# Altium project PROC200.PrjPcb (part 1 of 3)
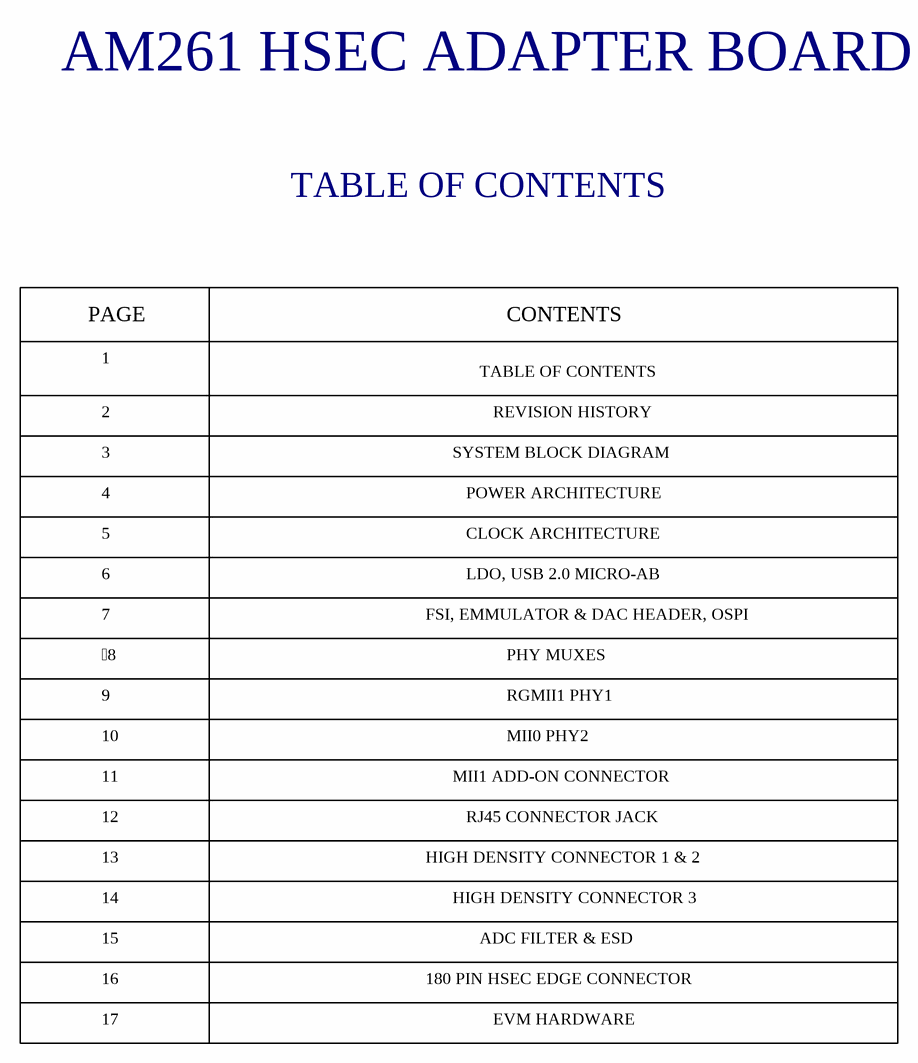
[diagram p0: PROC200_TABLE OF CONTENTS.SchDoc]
DrawnBy: Texas Instruments; EVM_orderable: HSEC180ADAPEVM-AM2; PCB_Rev: E1; PRJ_Customer: Public Release; PRJ_Number: PROC200; PRJ_Title: AM261 HSEC Adapter Board; SCH_REV: E1
18 sheets, 363 parts. Net scope: global (net labels, ports and power ports of the same name join across sheets).
Board file: PROC200E1.PcbDoc
Sheets:
  PROC200_TABLE OF CONTENTS.SchDoc
  PROC200_REVISION_HISTORY.SchDoc
  PROC200_SYSTEM_BLOCK_DIAGRAM.SchDoc
  PROC200_POWER_ARCHITECTURE.SchDoc
  PROC200_CLOCK_ARCHITECTURE.SchDoc
  PROC200_RESET_SIGNAL_ARCHITECTURE.SchDoc
  PROC200_LDO_USB_MICRO-AB.SchDoc
  PROC200_OSPI_FSI _DAC_Emmulator_Header.SchDoc
  PROC200_PHY_MUX.SchDoc
  PROC200_RGMII1_PHY1.SchDoc
  PROC200_MII0_PHY2.SchDoc
  PROC200_MII1_ADD_ON_CONN.SchDoc
  PROC200_RJ45_1_2.SchDoc
  PROC200_High_Density_conn1_2.SchDoc
  PROC200_High_Density_conn3.SchDoc
  PROC200_HSEC_ADC.SchDoc
  PROC200_180pin_Edge_Connector.SchDoc
  PROC200_EVM_Hardware.SchDoc

## Sheet PROC200_TABLE OF CONTENTS.SchDoc
size 431 x 279 mm; Date: Not shown in title block; ApprovedBy: Not shown in title block; CheckedBy: Not shown in title block; Author: Not shown in title block; CompanyName: Not shown in title block; Engineer: Not shown in title block; Organization: Not shown in title block; Address1: Not shown in title block; Address2: Not shown in title block; Address3: Not shown in title block; Address4: Not shown in title block; DocumentNumber: 1; Revision: Use project parameter SCH_Rev; SheetNumber: 1; SheetTotal: 17; PageSetup: Record=PageOptions¦CenterHorizontal=True¦CenterVertical=True¦PrintScale=1.00¦XCorrection=1.00¦YCorrection=1.00¦PrintKind=0¦BorderSize=5000000¦LeftOffset=0¦BottomOffset=0¦Orientation=2¦PaperLength=1000¦PaperWidth=1000¦Scale=100¦PaperSource=15¦PrintQuality=600¦MediaType=1¦DitherType=10¦PaperKind=Letter¦PrintScaleMode=1

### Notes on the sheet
- AM261 HSEC ADAPTER BOARD
- TABLE OF CONTENTS
- PAGE
- 1
- CONTENTS
- 2
- REVISION HISTORY
- 3
- 4
- SYSTEM BLOCK DIAGRAM
- POWER ARCHITECTURE
- 5
- 6
- LDO, USB 2.0 MICRO-AB
- CLOCK ARCHITECTURE
- 7
- FSI, EMMULATOR & DAC HEADER, OSPI
- 8
- 9
- PHY MUXES
- RGMII1 PHY1
- 10
- 11
- MII1 ADD-ON CONNECTOR
- MII0 PHY2
- 12
- RJ45 CONNECTOR JACK
- 13
- 14
- HIGH DENSITY CONNECTOR 1 & 2
- HIGH DENSITY CONNECTOR 3
- 15
- 16
- 180 PIN HSEC EDGE CONNECTOR
- ADC FILTER & ESD
- 17
- EVM HARDWARE

## Sheet PROC200_REVISION_HISTORY.SchDoc
size 431 x 279 mm; Date: Not shown in title block; ApprovedBy: Not shown in title block; CheckedBy: Not shown in title block; Author: Not shown in title block; CompanyName: Not shown in title block; Engineer: Not shown in title block; Organization: Not shown in title block; Address1: Not shown in title block; Address2: Not shown in title block; Address3: Not shown in title block; Address4: Not shown in title block; DocumentNumber: 2; Revision: Use project parameter SCH_Rev; SheetNumber: 2; SheetTotal: 17; PageSetup: Record=PageOptions¦CenterHorizontal=True¦CenterVertical=True¦PrintScale=1.00¦XCorrection=1.00¦YCorrection=1.00¦PrintKind=0¦BorderSize=5000000¦LeftOffset=0¦BottomOffset=0¦Orientation=2¦PaperLength=1000¦PaperWidth=1000¦Scale=100¦PaperSource=15¦PrintQuality=600¦MediaType=1¦DitherType=10¦PaperKind=Letter¦PrintScaleMode=1
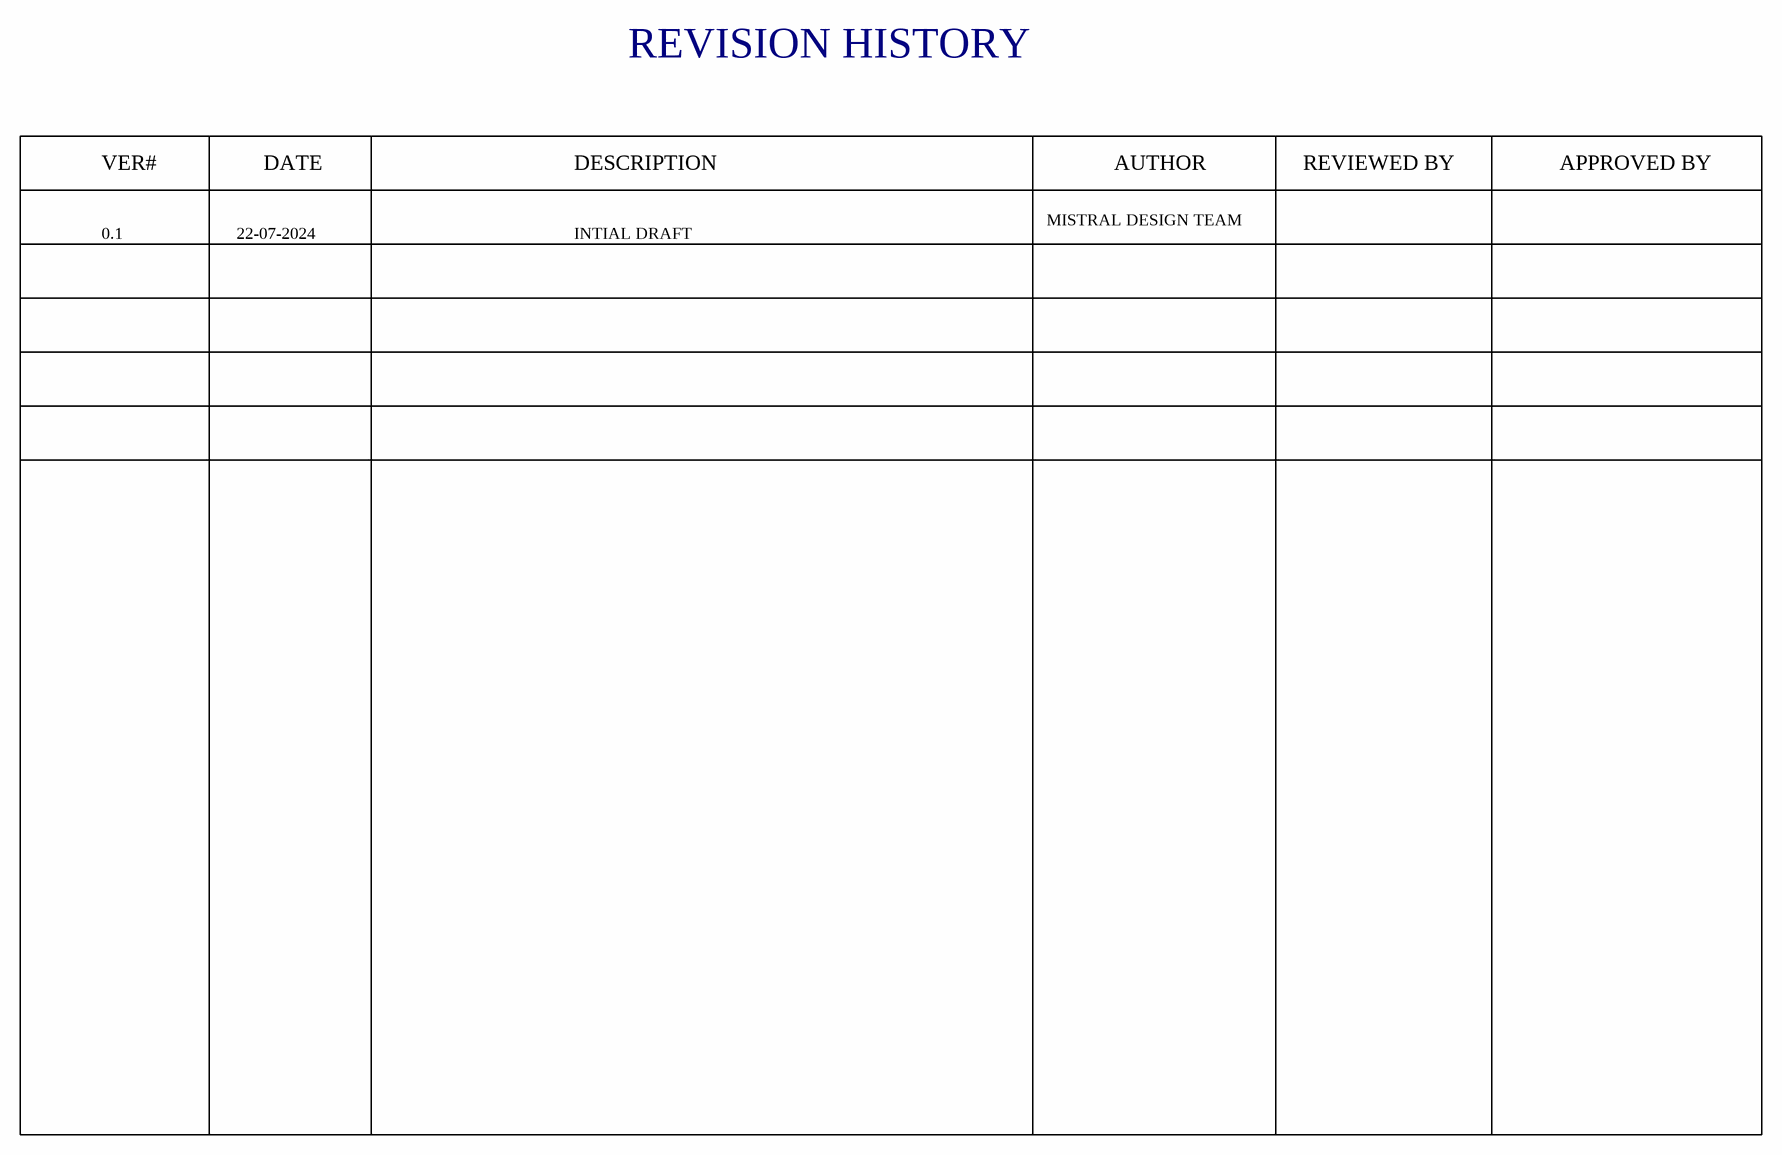
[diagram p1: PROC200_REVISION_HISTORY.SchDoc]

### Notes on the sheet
- REVISION HISTORY
- VER#
- DATE
- DESCRIPTION
- AUTHOR
- REVIEWED BY
- APPROVED BY
- 0.1
- 22-07-2024
- INTIAL DRAFT
- MISTRAL DESIGN TEAM

## Sheet PROC200_SYSTEM_BLOCK_DIAGRAM.SchDoc
size 431 x 279 mm; Date: Not shown in title block; ApprovedBy: Not shown in title block; CheckedBy: Not shown in title block; Author: Not shown in title block; CompanyName: Not shown in title block; Engineer: Not shown in title block; Organization: Not shown in title block; Address1: Not shown in title block; Address2: Not shown in title block; Address3: Not shown in title block; Address4: Not shown in title block; DocumentNumber: 3; Revision: Use project parameter SCH_Rev; SheetNumber: 3; SheetTotal: 17; PageSetup: Record=PageOptions¦CenterHorizontal=True¦CenterVertical=True¦PrintScale=1.00¦XCorrection=1.00¦YCorrection=1.00¦PrintKind=0¦BorderSize=5000000¦LeftOffset=0¦BottomOffset=0¦Orientation=2¦PaperLength=1000¦PaperWidth=1000¦Scale=100¦PaperSource=15¦PrintQuality=600¦MediaType=1¦DitherType=10¦PaperKind=Letter¦PrintScaleMode=1
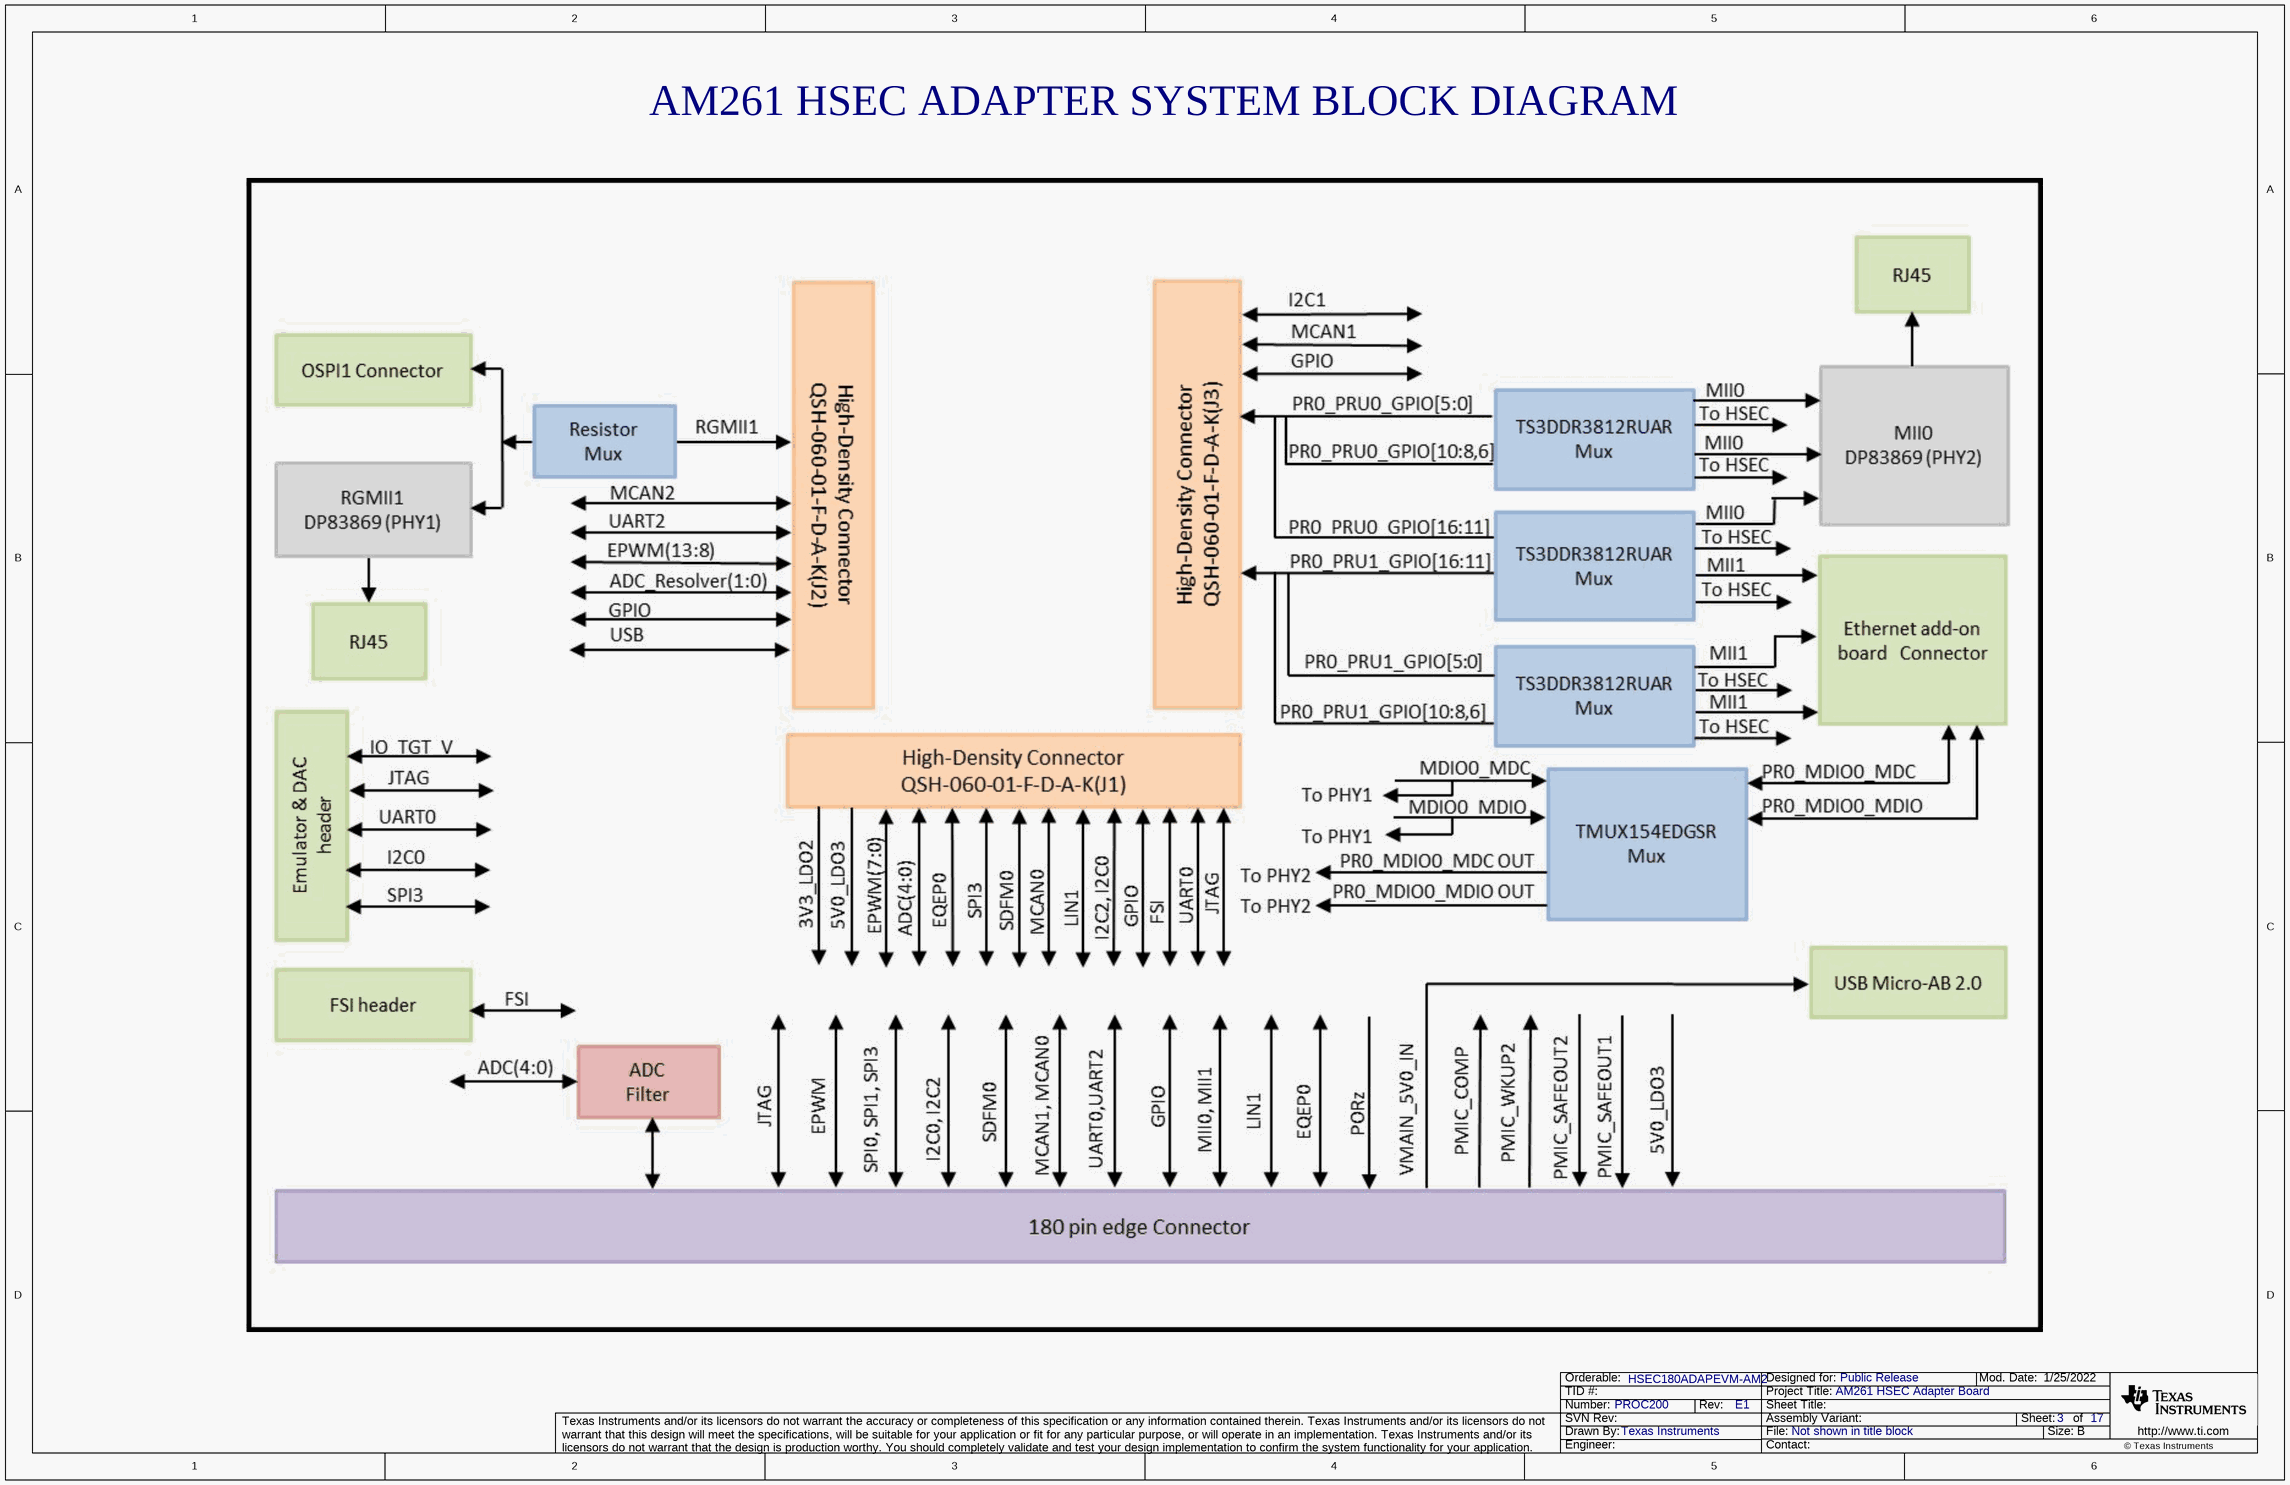
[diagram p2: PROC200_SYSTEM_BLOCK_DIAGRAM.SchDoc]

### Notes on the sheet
- AM261 HSEC ADAPTER SYSTEM BLOCK DIAGRAM

## Sheet PROC200_POWER_ARCHITECTURE.SchDoc
size 431 x 279 mm; Date: Not shown in title block; ApprovedBy: Not shown in title block; CheckedBy: Not shown in title block; Author: Not shown in title block; CompanyName: Not shown in title block; Engineer: Not shown in title block; Organization: Not shown in title block; Address1: Not shown in title block; Address2: Not shown in title block; Address3: Not shown in title block; Address4: Not shown in title block; DocumentNumber: 4; Revision: Use project parameter SCH_Rev; SheetNumber: 4; SheetTotal: 17; PageSetup: Record=PageOptions¦CenterHorizontal=True¦CenterVertical=True¦PrintScale=1.00¦XCorrection=1.00¦YCorrection=1.00¦PrintKind=0¦BorderSize=5000000¦LeftOffset=0¦BottomOffset=0¦Orientation=2¦PaperLength=1000¦PaperWidth=1000¦Scale=100¦PaperSource=15¦PrintQuality=600¦MediaType=1¦DitherType=10¦PaperKind=Letter¦PrintScaleMode=1
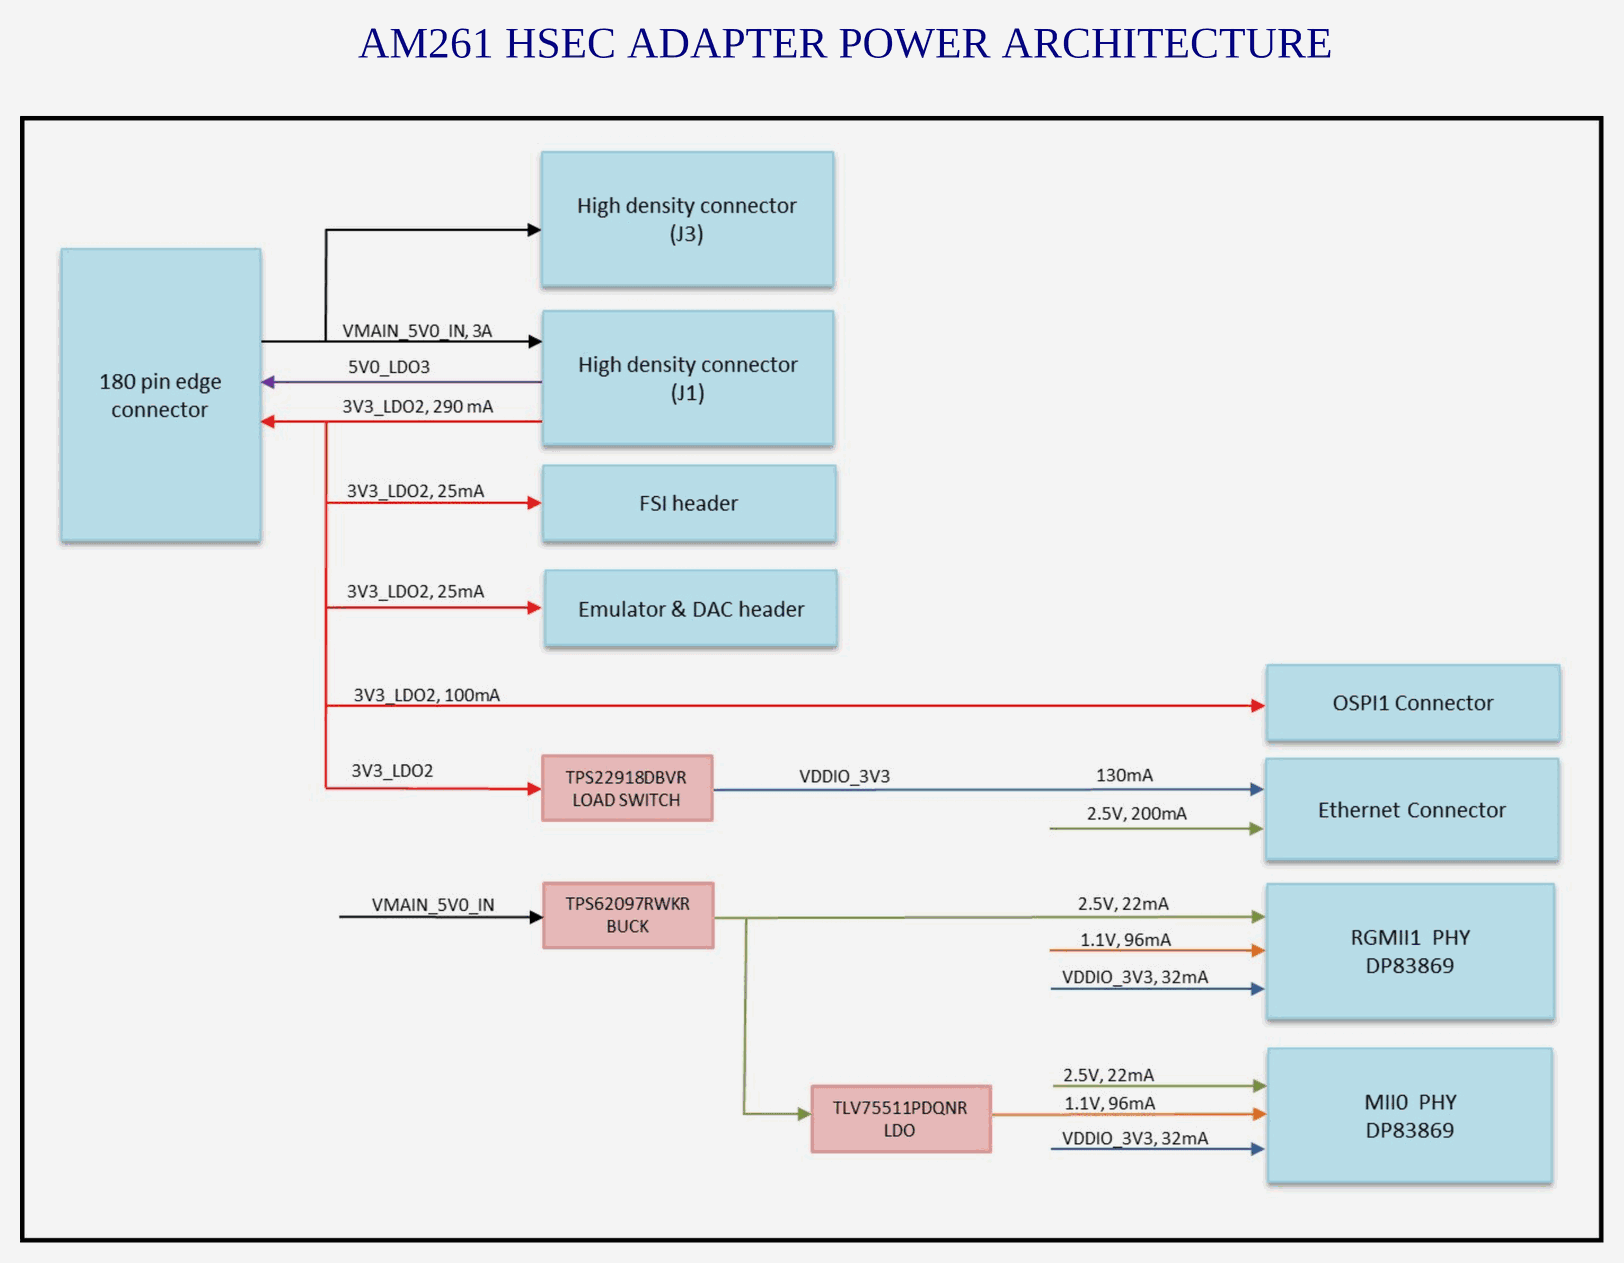
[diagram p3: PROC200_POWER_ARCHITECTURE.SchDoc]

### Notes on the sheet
- AM261 HSEC ADAPTER POWER ARCHITECTURE

## Sheet PROC200_CLOCK_ARCHITECTURE.SchDoc
size 431 x 279 mm; Date: Not shown in title block; ApprovedBy: Not shown in title block; CheckedBy: Not shown in title block; Author: Not shown in title block; CompanyName: Not shown in title block; Engineer: Not shown in title block; Organization: Not shown in title block; Address1: Not shown in title block; Address2: Not shown in title block; Address3: Not shown in title block; Address4: Not shown in title block; DocumentNumber: 1; Revision: Use project parameter SCH_Rev; SheetNumber: 5; SheetTotal: 17; PageSetup: Record=PageOptions¦CenterHorizontal=True¦CenterVertical=True¦PrintScale=1.00¦XCorrection=1.00¦YCorrection=1.00¦PrintKind=0¦BorderSize=5000000¦LeftOffset=0¦BottomOffset=0¦Orientation=2¦PaperLength=1000¦PaperWidth=1000¦Scale=100¦PaperSource=15¦PrintQuality=600¦MediaType=1¦DitherType=10¦PaperKind=Letter¦PrintScaleMode=1
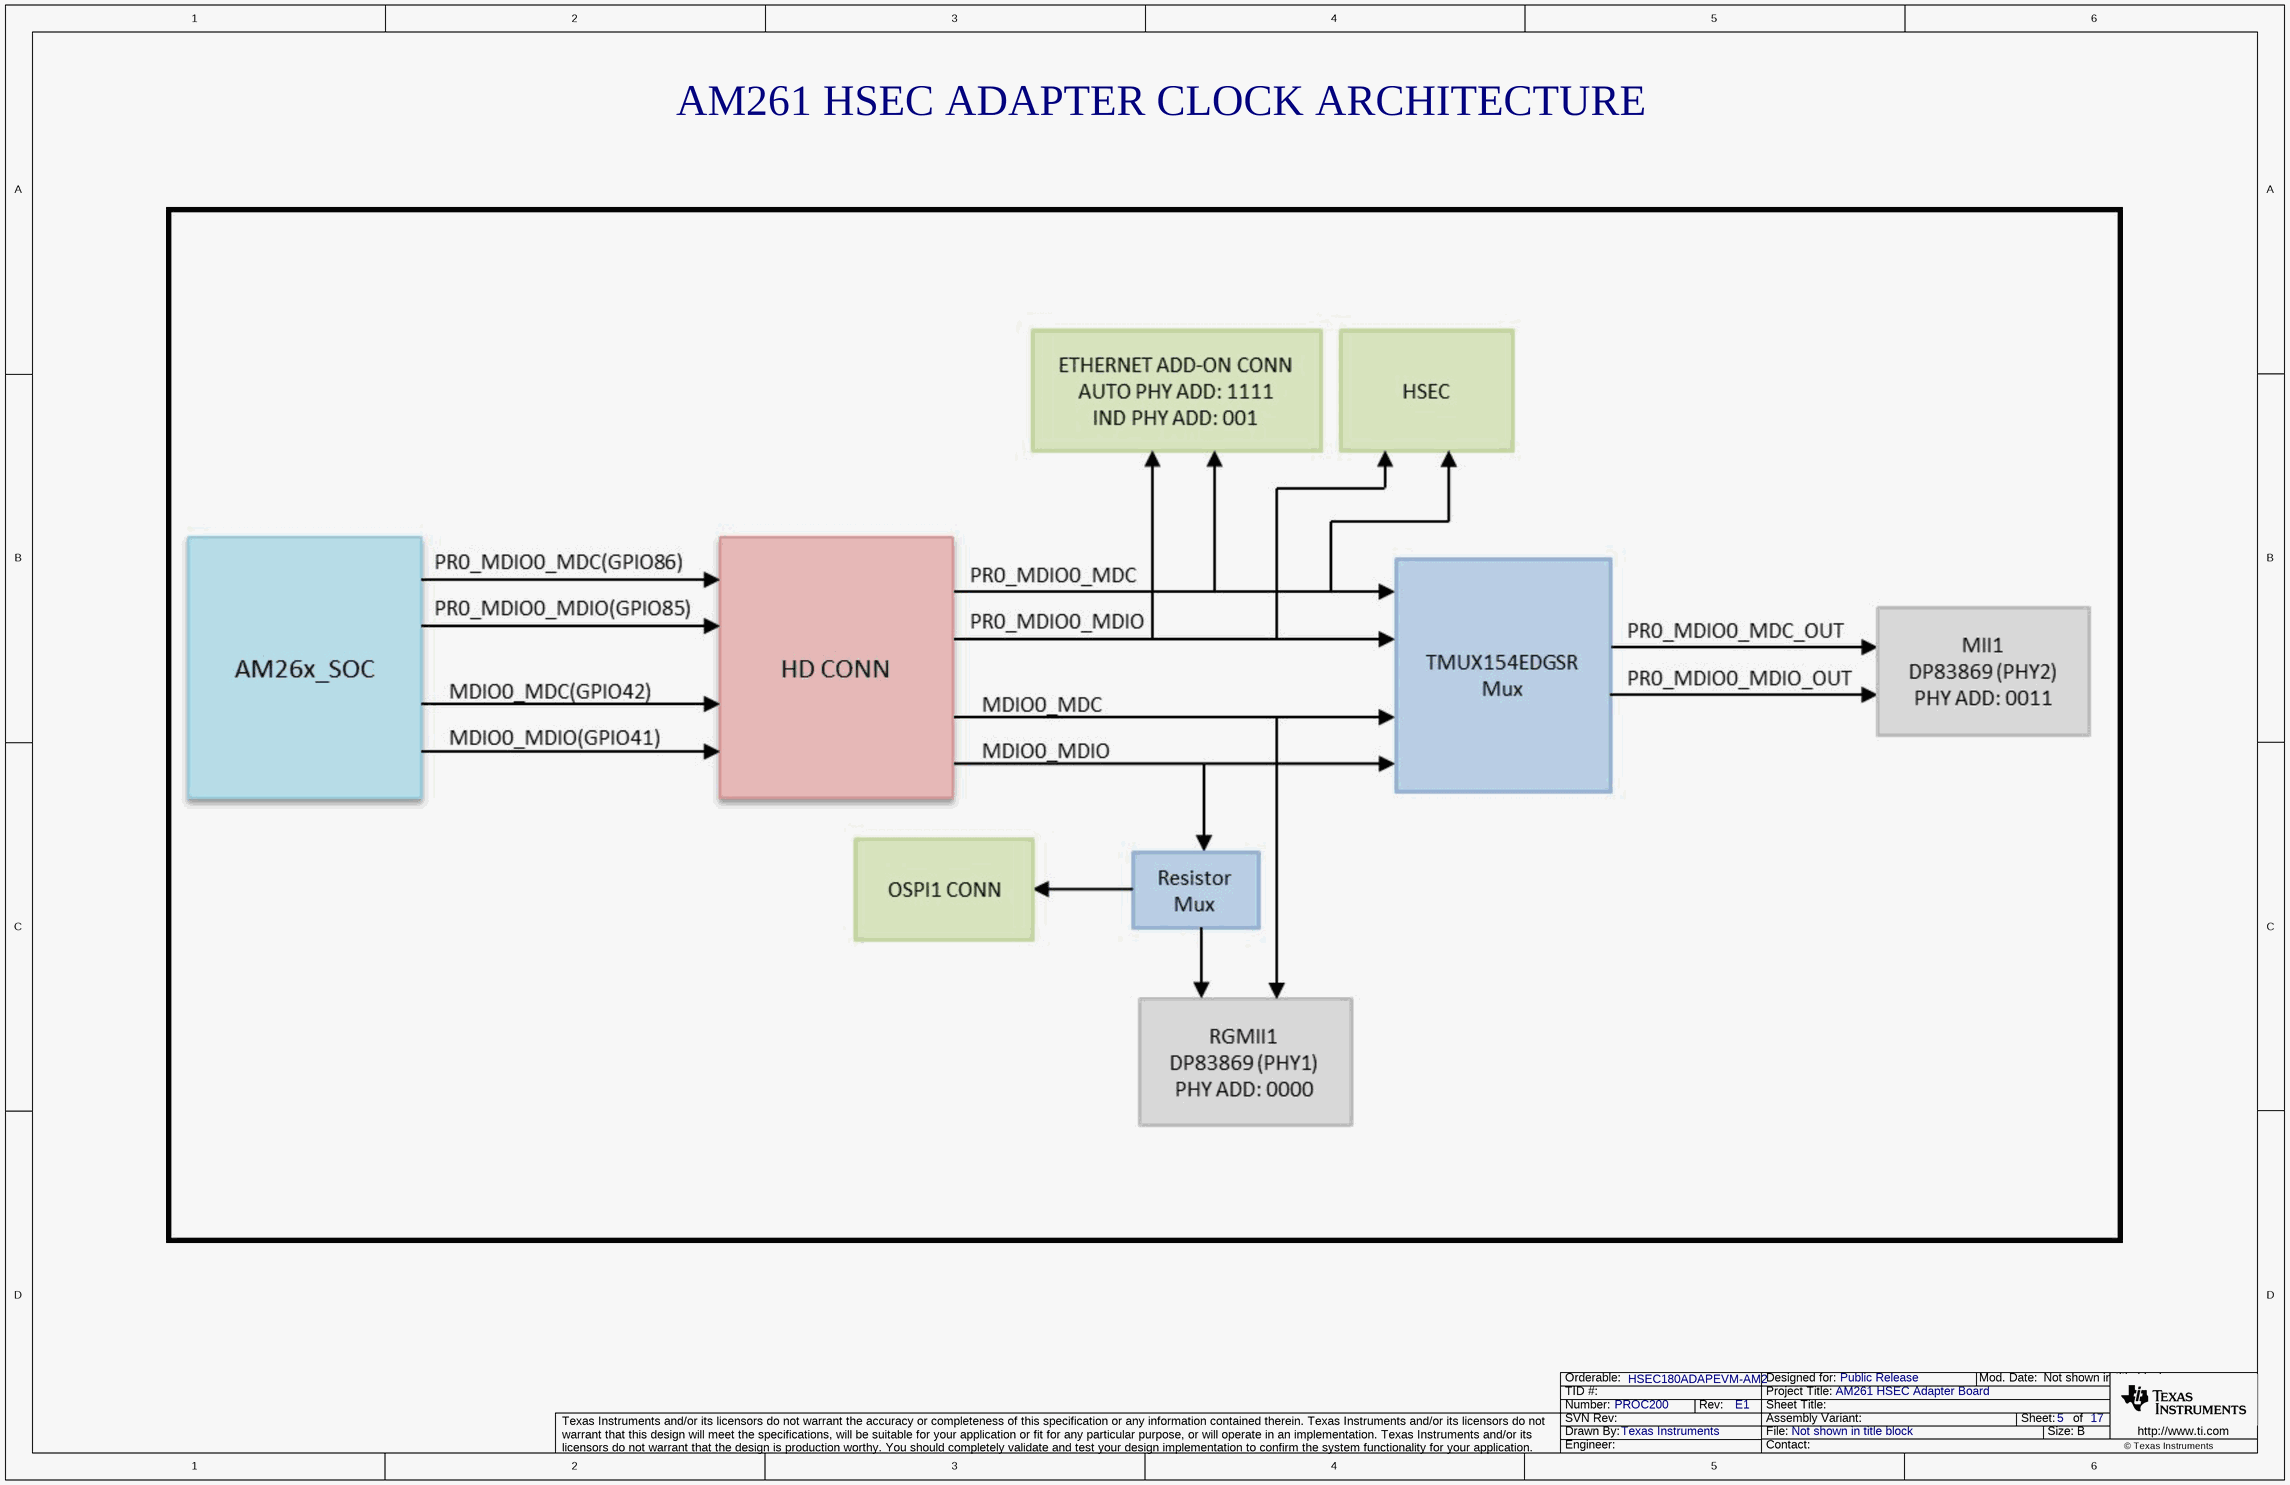
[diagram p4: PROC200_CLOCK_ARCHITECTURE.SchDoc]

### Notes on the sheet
- AM261 HSEC ADAPTER CLOCK ARCHITECTURE

## Sheet PROC200_RESET_SIGNAL_ARCHITECTURE.SchDoc
size 431 x 279 mm; Date: Not shown in title block; ApprovedBy: Not shown in title block; CheckedBy: Not shown in title block; Author: Not shown in title block; CompanyName: Not shown in title block; Engineer: Not shown in title block; Organization: Not shown in title block; Address1: Not shown in title block; Address2: Not shown in title block; Address3: Not shown in title block; Address4: Not shown in title block; DocumentNumber: 1; Revision: Use project parameter SCH_Rev; SheetNumber: 6; SheetTotal: 18; PageSetup: Record=PageOptions¦CenterHorizontal=True¦CenterVertical=True¦PrintScale=1.00¦XCorrection=1.00¦YCorrection=1.00¦PrintKind=0¦BorderSize=5000000¦LeftOffset=0¦BottomOffset=0¦Orientation=2¦PaperLength=1000¦PaperWidth=1000¦Scale=100¦PaperSource=15¦PrintQuality=600¦MediaType=1¦DitherType=10¦PaperKind=Letter¦PrintScaleMode=1
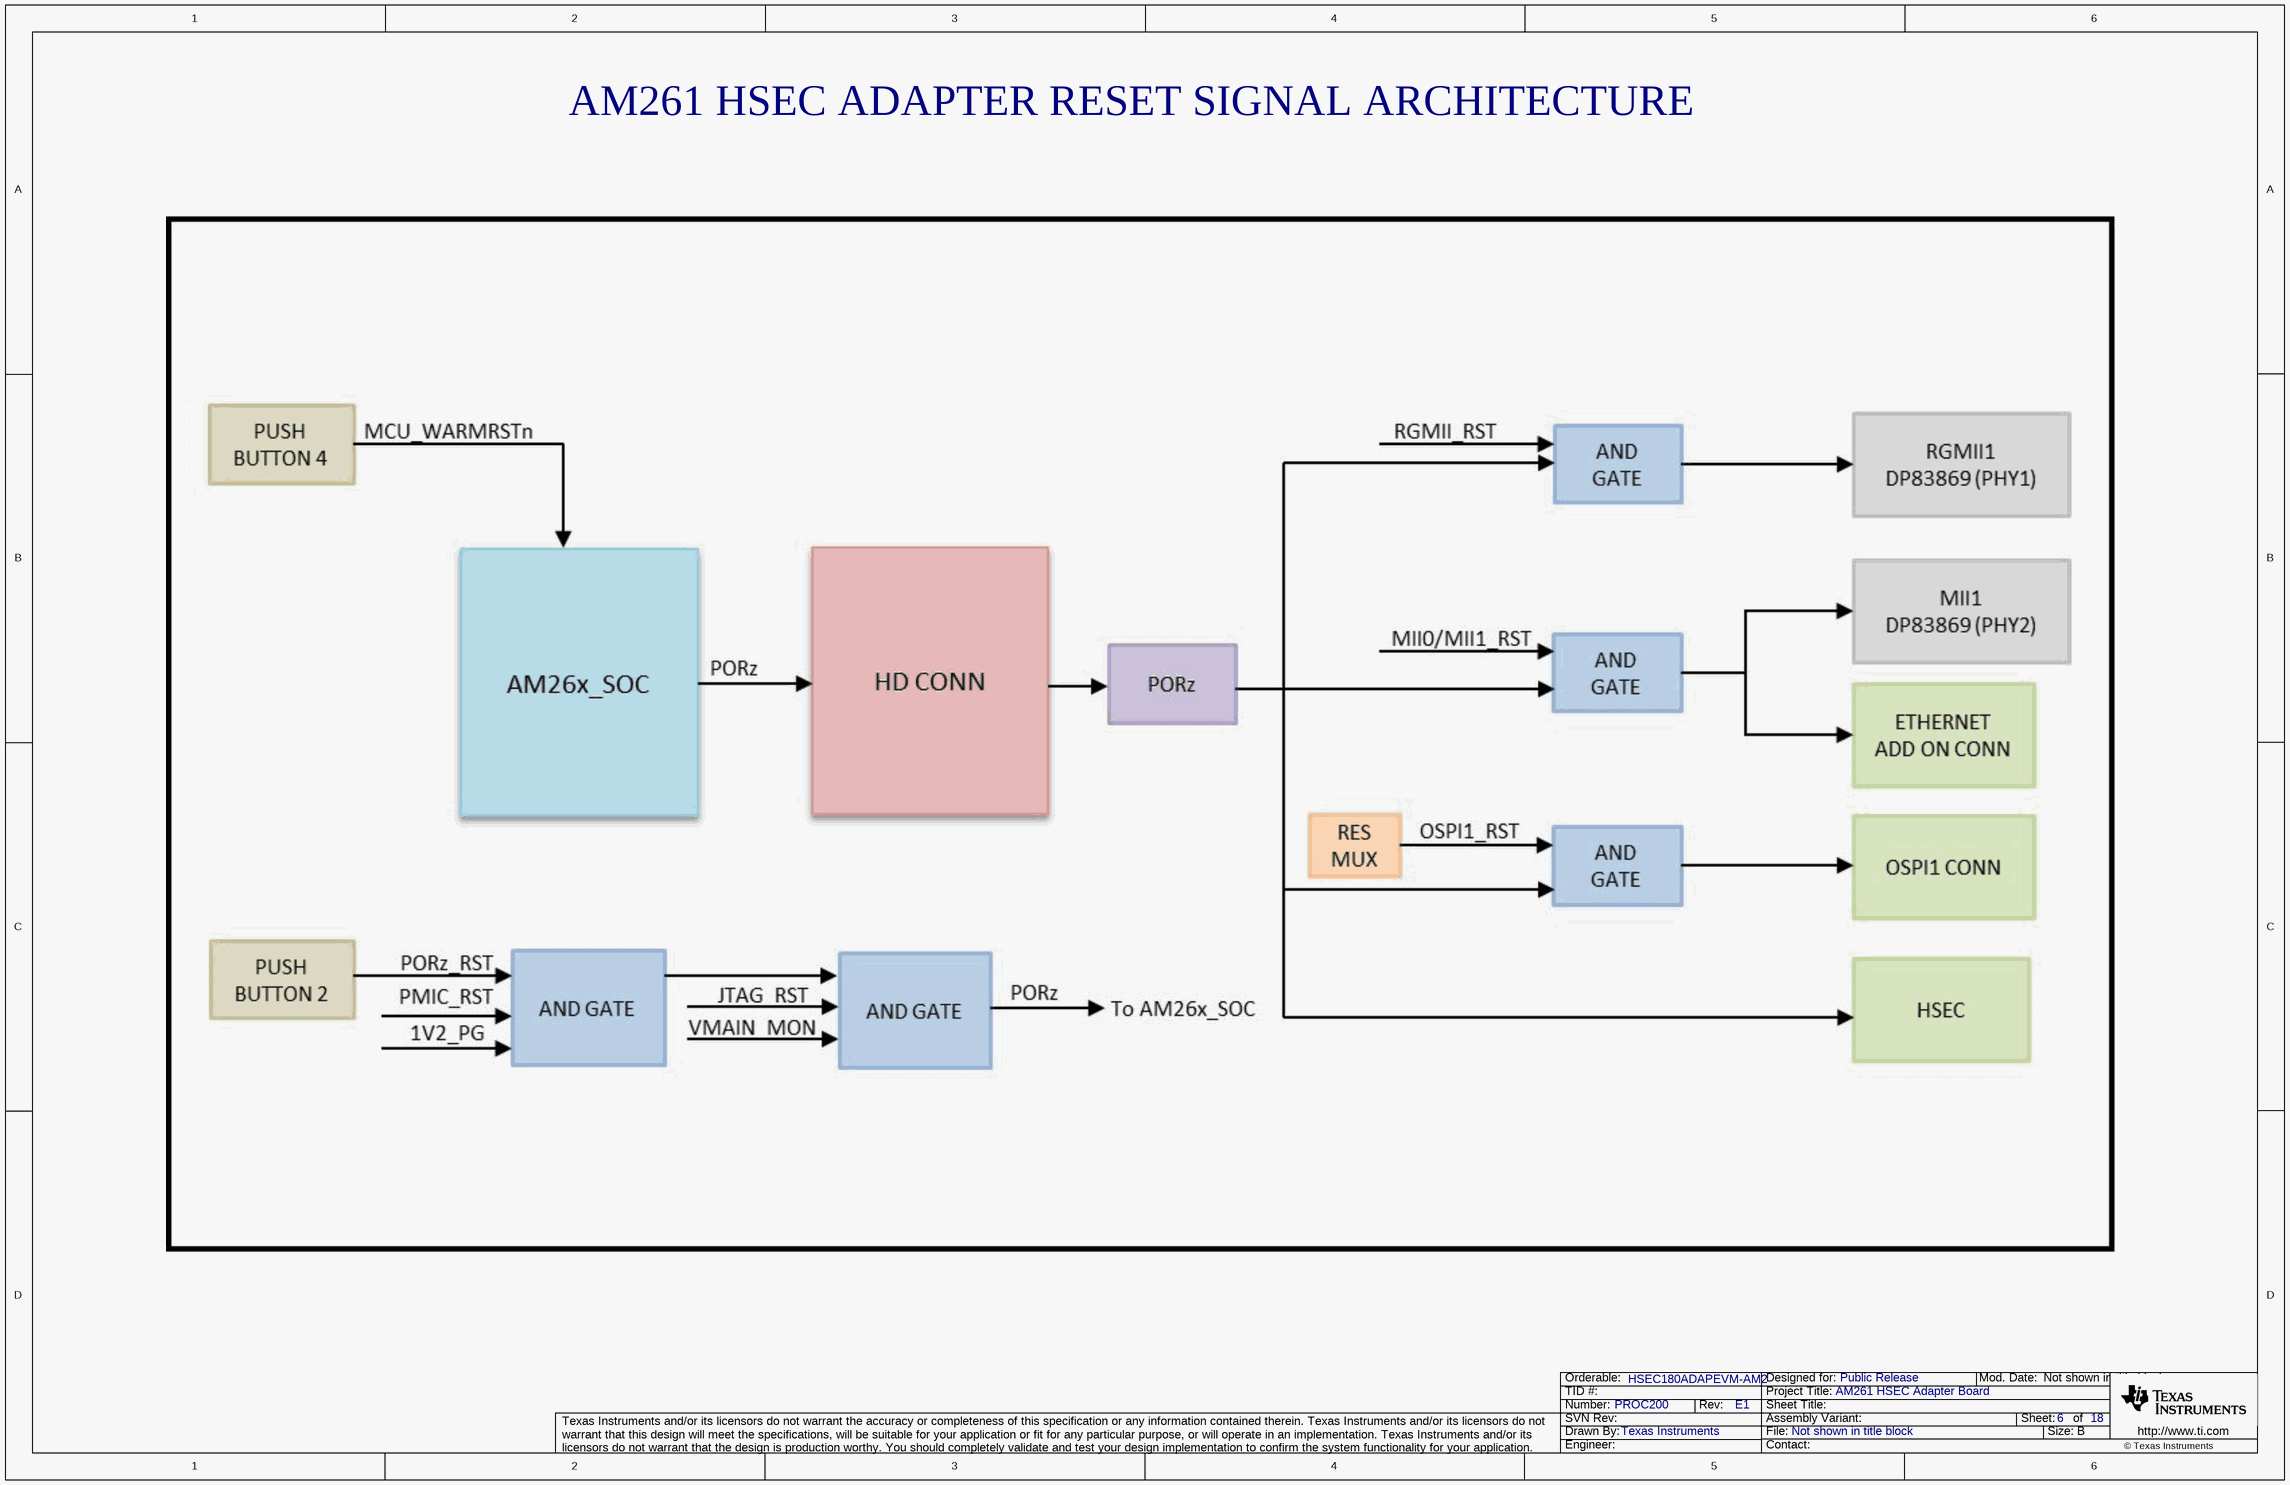
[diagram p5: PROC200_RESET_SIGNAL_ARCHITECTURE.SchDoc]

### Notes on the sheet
- AM261 HSEC ADAPTER RESET SIGNAL ARCHITECTURE

## Sheet PROC200_LDO_USB_MICRO-AB.SchDoc
size 431 x 279 mm; SheetNumber: 7; SheetTotal: 18
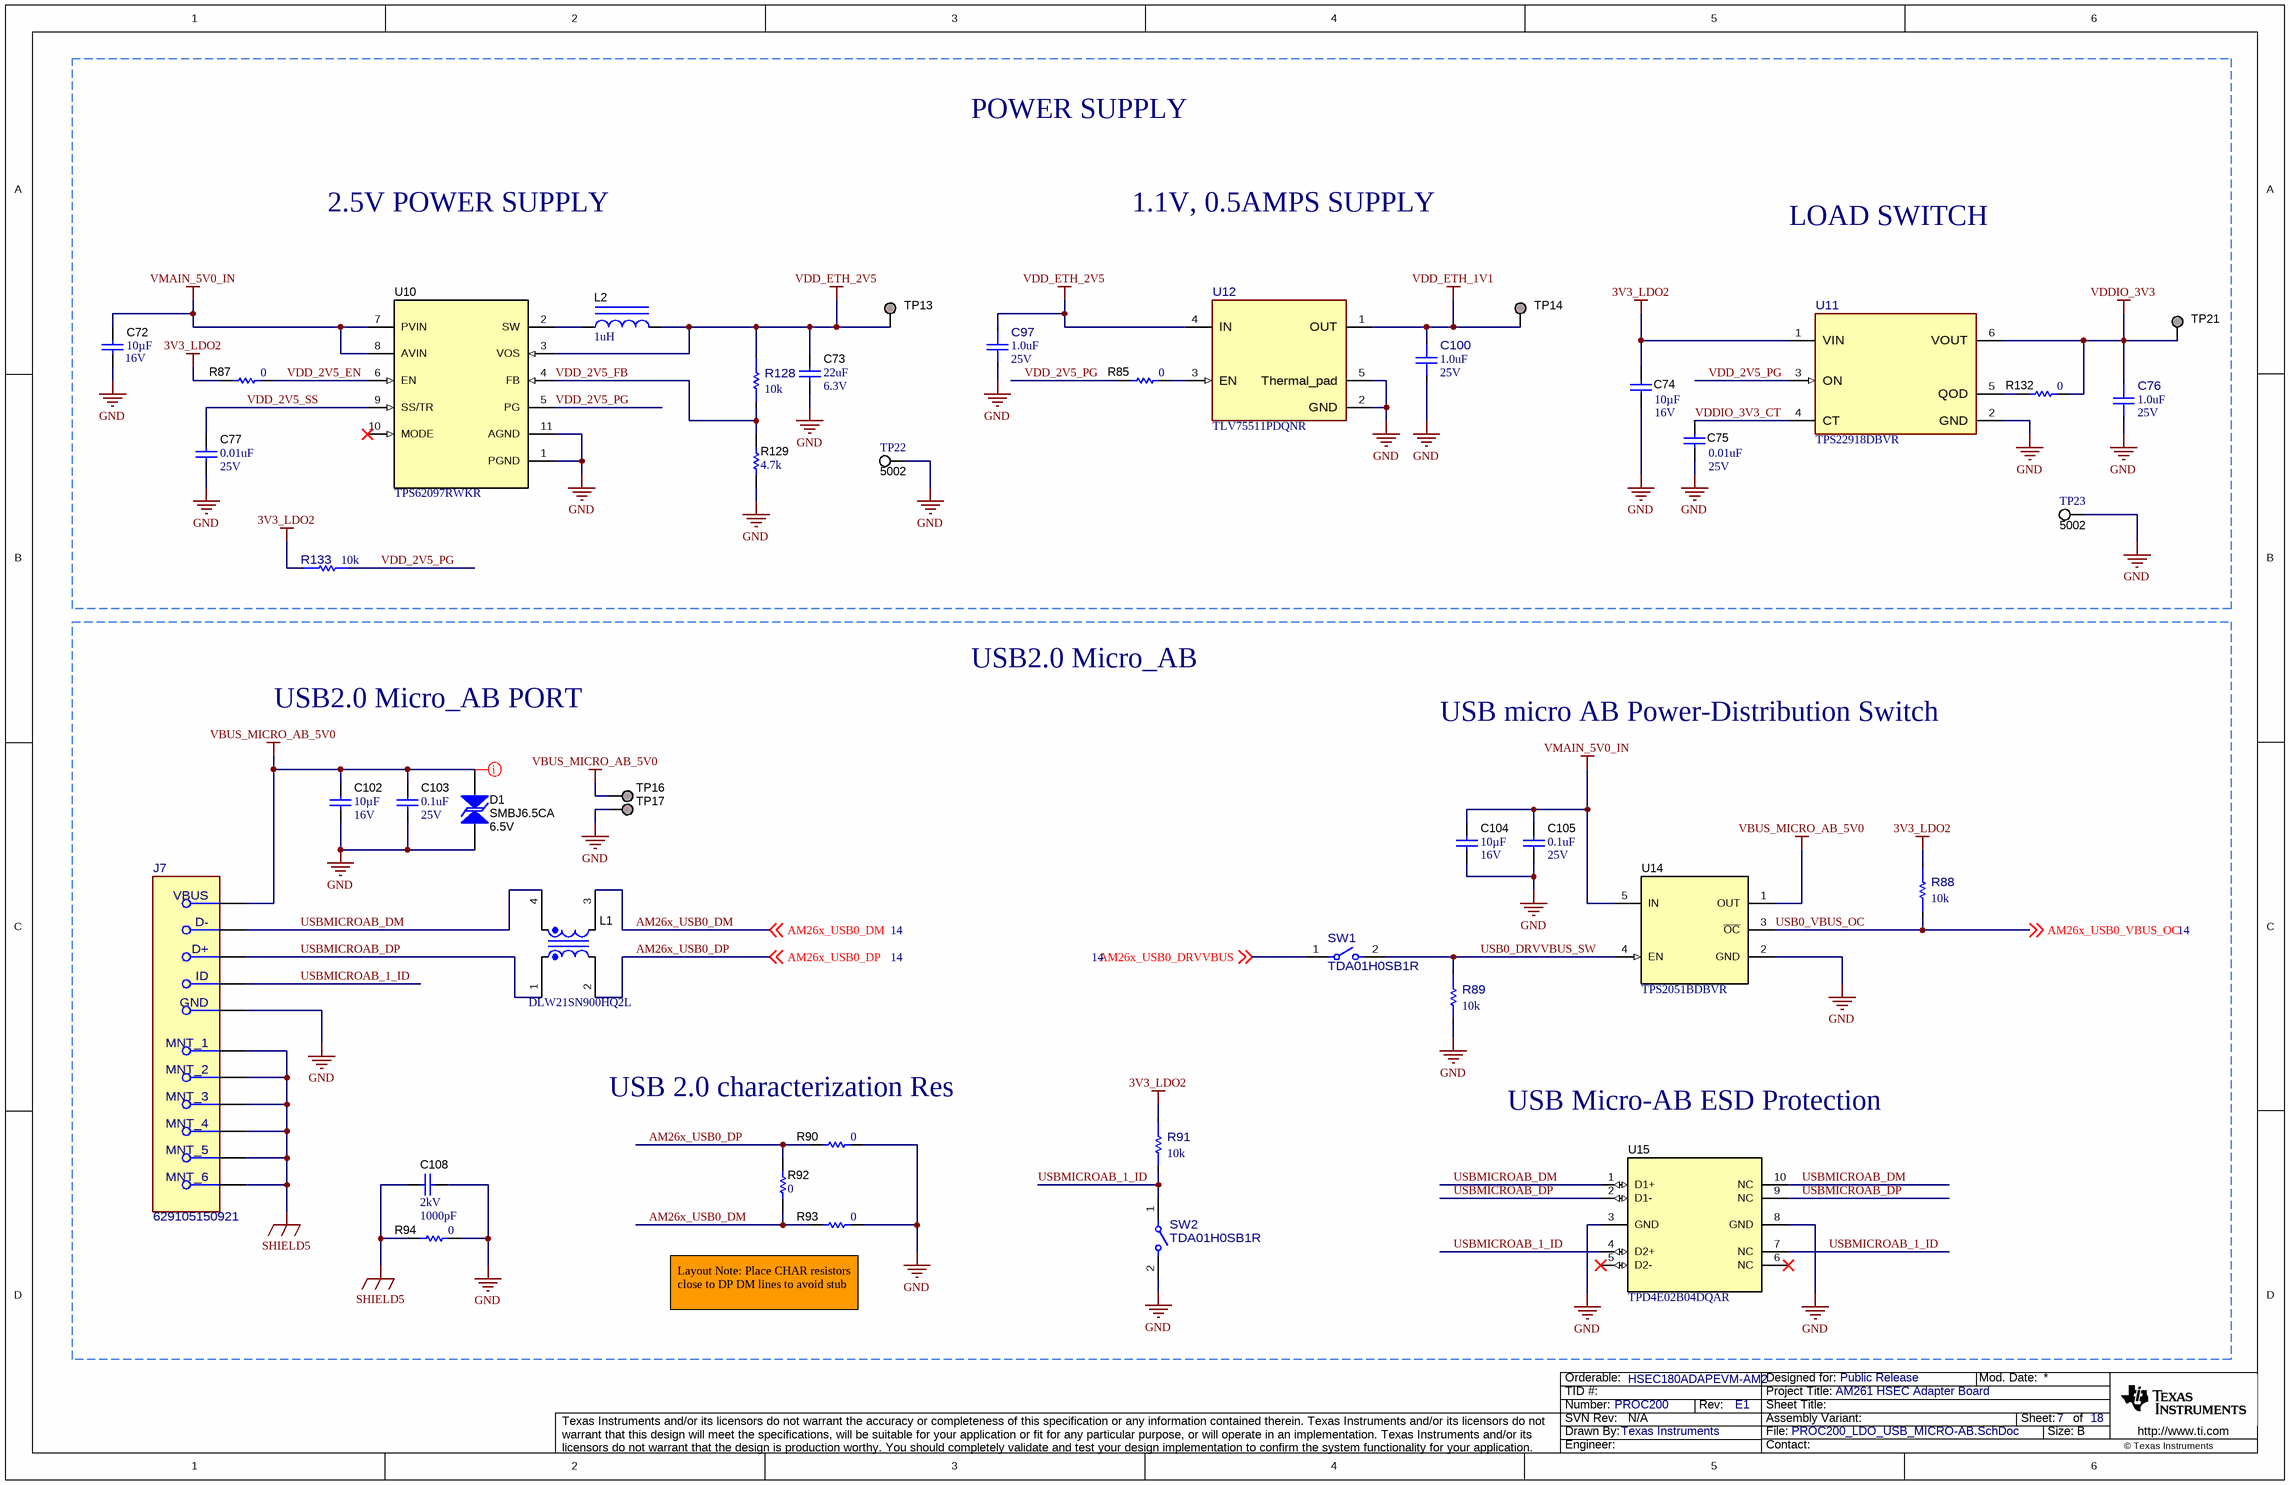
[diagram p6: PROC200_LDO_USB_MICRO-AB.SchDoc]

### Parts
C72  VDC_V: 16V  ValueDisplayed: 10µF  [0603]  (hidden comment: GRM188C81C106MA73D)
C73  VDC_V: 6.3V  ValueDisplayed: 22uF  [0603]  (hidden comment: GRM188R60J226MEA0D)
C74  VDC_V: 16V  ValueDisplayed: 10µF  [0603]  (hidden comment: GRM188C81C106MA73D)
C75  Value2: 25V  ValueDisplayed: 0.01uF  [0402]  (hidden comment: GCM155R71E103KA37D)
C76  ValueDisplayed: 1.0uF  VDC_V: 25V  [FP-GRM155C81E105KE11D_0402-MFG]  (hidden comment: GRM155C81E105KE11D)
C77  Value2: 25V  ValueDisplayed: 0.01uF  [0402]  (hidden comment: GCM155R71E103KA37D)
C97  ValueDisplayed: 1.0uF  VDC_V: 25V  [FP-GRM155C81E105KE11D_0402-MFG]  (hidden comment: GRM155C81E105KE11D)
C100  ValueDisplayed: 1.0uF  VDC_V: 25V  [FP-GRM155C81E105KE11D_0402-MFG]  (hidden comment: GRM155C81E105KE11D)
C102  VDC_V: 16V  ValueDisplayed: 10µF  [0603]  (hidden comment: GRM188C81C106MA73D)
C103  VDC_V: 25V  ValueDisplayed: 0.1uF  [0402]  (hidden comment: GRM155R71E104KE14D)
C104  VDC_V: 16V  ValueDisplayed: 10µF  [0603]  (hidden comment: GRM188C81C106MA73D)
C105  Value2: 25V  ValueDisplayed: 0.1uF  [0402]  (hidden comment: GRM155R71E104KE14D)
C108  VDC_V: 2kV  ValueDisplayed: 1000pF  [1808]  (hidden comment: GR442QR73D102KW01L)
D1  SMBJ6.5CA  value 6.5V  [SMB-Bi]
J7  629105150921  [FP-629105150921_CONN_PTH_USB_8MM0_5MM6-MFG]
L1  DLW21SN900HQ2L  [IND_DLW21S]
L2  ValueDisplayed: 1uH  [IHLP-2020BZ]  (hidden comment: IHLP2020BZER1R0M01)
R85  ValueDisplayed: 0  [0402]  (hidden comment: ERJ-2GE0R00X)
R87  ValueDisplayed: 0  [0402]  (hidden comment: ERJ-2GE0R00X)
R88  value 10k  [FP-RC0402JR-0710KL_0402-MFG]  (hidden comment: RC0402JR-0710KL)
R89  value 10k  [FP-RC0402JR-0710KL_0402-MFG]  (hidden comment: RC0402JR-0710KL)
R90  ValueDisplayed: 0  [0402]  (hidden comment: ERJ-2GE0R00X)
R91  value 10k  [FP-RC0402JR-0710KL_0402-MFG]  (hidden comment: RC0402JR-0710KL)
R92  ValueDisplayed: 0  [0402]  (hidden comment: ERJ-2GE0R00X)
R93  ValueDisplayed: 0  [0402]  (hidden comment: ERJ-2GE0R00X)
R94  ValueDisplayed: 0  [0805_HV]  (hidden comment: ERJ-6GEY0R00V)
R128  value 10k  [FP-RC0402JR-0710KL_0402-MFG]  (hidden comment: RC0402JR-0710KL)
R129  ValueDisplayed: 4.7k  [0402]  (hidden comment: CRCW04024K70JNED)
R132  ValueDisplayed: 0  [0402]  (hidden comment: ERJ-2GE0R00X)
R133  value 10k  [FP-RC0402JR-0710KL_0402-MFG]  (hidden comment: RC0402JR-0710KL)
SW1  TDA01H0SB1R  [FP-TDA01H0SB1R_SMT_SW_2MM40_6MM20-MFG]
SW2  TDA01H0SB1R  [FP-TDA01H0SB1R_SMT_SW_2MM40_6MM20-MFG]
TP13  TESTPOINT  [TP_25MIL-SMT]  (value not drawn)  (no BOM)
TP14  TESTPOINT  [TP_25MIL-SMT]  (value not drawn)  (no BOM)
TP16  TESTPOINT  [TP_25MIL-SMT]  (value not drawn)  (no BOM)
TP17  TESTPOINT  [TP_25MIL-SMT]  (value not drawn)  (no BOM)
TP21  TESTPOINT  [TP_25MIL-SMT]  (value not drawn)  (no BOM)
TP22  5002  [Keystone5002]
TP23  5002  [Keystone5002]
U10  TPS62097RWKR  [RWK0011B]
U11  TPS22918DBVR  [DBV0006A-MFG]
U12  TLV75511PDQNR  [DQN0004A-MFG]
U14  TPS2051BDBVR  [DBV0005A_N]
U15  TPD4E02B04DQAR  [DQA0010A]

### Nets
3V3_LDO2: C74.2 R87.1 R88.1 R91.1 R133.1 U11.1(VIN)
GND: C72.1 C73.1 C74.1 C75.2 C76.2 C77.2 C97.2 C100.2 C102.1 C103.2 C104.1 C105.1 C108.1 D1.1 J7.5(GND) R89.2 R90.2 R93.2 R94.2 R129.2 SW2.2 TP17.1 TP22.1 TP23.1 U10.1(PGND) U10.11(AGND) U11.2(GND) U12.2(GND) U12.5(Thermal_pad) U14.2(GND) U15.3(GND) U15.8(GND)
SHIELD5: C108.2 J7.6(MNT_1) J7.7(MNT_2) J7.8(MNT_3) J7.9(MNT_4) J7.10(MNT_5) J7.11(MNT_6) R94.1
VBUS_MICRO_AB_5V0: C102.2 C103.1 D1.2 J7.1(VBUS) TP16.1 U14.1(OUT)
VDD_ETH_1V1: C100.1 TP14.1 U12.1(OUT)
VDD_ETH_2V5: C73.2 C97.1 L2.2 R128.1 TP13.1 U10.3(VOS) U12.4(IN)
VDDIO_3V3: C76.1 R132.2 TP21.1 U11.6(VOUT)
VMAIN_5V0_IN: C72.2 C104.2 C105.2 U10.7(PVIN) U10.8(AVIN) U14.5(IN)
AM26x_USB0_DM: L1.3 R92.1 R93.1 ; off-sheet AM26x_USB0_DM
AM26x_USB0_DP: L1.2 R90.1 R92.2 ; off-sheet AM26x_USB0_DP
AM26x_USB0_DRVVBUS: SW1.1 ; off-sheet AM26x_USB0_DRVVBUS
USB0_DRVVBUS_SW: R89.1 SW1.2 U14.4(EN)
USB0_VBUS_OC: R88.2 U14.3(~{OC}) ; off-sheet AM26x_USB0_VBUS_OC  [also labelled AM26x_USB0_VBUS_OC]
USBMICROAB_1_ID: J7.4(ID) R91.2 SW2.1 U15.4(D2+) U15.7(NC)
USBMICROAB_DM: J7.2(D-) L1.4 U15.1(D1+) U15.10(NC)
USBMICROAB_DP: J7.3(D+) L1.1 U15.2(D1-) U15.9(NC)
VDD_2V5_EN: R87.2 U10.6(EN)
VDD_2V5_FB: R128.2 R129.1 U10.4(FB)
VDD_2V5_PG: R85.1 R133.2 U10.5(PG) U11.3(ON)
VDD_2V5_SS: C77.1 U10.9(SS/TR)
VDDIO_3V3_CT: C75.1 U11.4(CT)
NetL2_1: L2.1 U10.2(SW)
NetR85_2: R85.2 U12.3(EN)
NetR132_1: R132.1 U11.5(QOD)

Not connected (* = marked no-connect by the designer): U10 10(MODE)*; U15 5(D2-)* 6(NC)*

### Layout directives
net class POWER: VBUS_MICRO_AB_5V0

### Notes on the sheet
- POWER SUPPLY
- 2.5V POWER SUPPLY
- 1.1V, 0.5AMPS SUPPLY
- LOAD SWITCH
- USB2.0 Micro_AB
- USB2.0 Micro_AB PORT
- USB micro AB Power-Distribution Switch
- (near R90) USB 2.0 characterization Res
- USB Micro-AB ESD Protection
- (near R93) Layout Note: Place CHAR resistors close to DP DM lines to avoid stub

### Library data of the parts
C72 C74 C102 C104 = CMP-0086062-1: CAP, CERM, 10 µF, 16 V,+/- 20%, X6S, 0603; Manufacturer: MuRata; U/M: EA; AEC Category: Q200; SizeX_mm: 1.6; SizeY_mm: 0.8; SizeZ_mm: 1; Value: 10uF; SizeArea_mm2: 1.28; TaMin_C: -55°C; Polarized: N; SizeAreaWB_mm2: 4.68; TaMax_C: 105°C
C73 = CMP-0007306-5: CAP, CERM, 22 uF, 6.3 V, +/- 20%, X5R, 0603; Manufacturer: MuRata; TaMin_C: -55°C; Polarized: N; SizeAreaWB_mm2: 4.68; Value1: Unknown; U/M: EA; Value: 22uF; TaMax_C: 85°C; SizeZ_mm: 1; SizeX_mm: 1.6; SizeY_mm: 0.8; SizeArea_mm2: 1.28; Cap_F: 22µF; AEC Category: Q200
C75 C77 = CMP-0006352-2: CAP, CERM, 0.01 uF, 25 V, +/- 10%, X7R, 0402; Manufacturer: MuRata; TaMin_C: -55°C; Polarized: N; SizeAreaWB_mm2: 3; Value1: Unknown; U/M: EA; Value: 0.01uF; TaMax_C: 125°C; SizeZ_mm: 0.6; SizeX_mm: 1; SizeY_mm: 0.5; Cap_F: 10nF; AEC Category: Q200
C76 C97 C100 = CMP-0121658-2: Chip Multilayer Ceramic Capacitors for General Purpose, 0402, 1.0uF, X6S, 22%, 10%, 25V; Manufacturer: Murata; AEC Qualified: No; Cap_F: 1µF; SizeZ_mm: 0.6mm; Value: 1µF
C103 = CMP-0006659-2: CAP, CERM, 0.1 uF, 25 V, +/- 10%, X7R, 0402; Manufacturer: MuRata; TaMin_C: -55°C; Polarized: N; SizeAreaWB_mm2: 3; Value1: Unknown; U/M: EA; Value: 0.1uF; TaMax_C: 125°C; SizeZ_mm: 0.6; SizeX_mm: 1; SizeY_mm: 0.5; Cap_F: 100nF; AEC Category: Q200
C105 = CMP-0006659-2: CAP, CERM, 0.1 uF, 25 V, +/- 10%, X7R, 0402; Manufacturer: MuRata; TaMin_C: -55°C; Polarized: N; SizeAreaWB_mm2: 3; U/M: EA; Value: 0.1uF; TaMax_C: 125°C; SizeZ_mm: 0.6; SizeX_mm: 1; SizeY_mm: 0.5; Cap_F: 100nF; AEC Category: Q200; Value1: Unknown
C108 = CMP-0009436-2: CAP, CERM, 1000 pF, 2000 V, +/- 10%, X7R, 1808; Manufacturer: MuRata; TaMin_C: -55°C; Polarized: N; SizeAreaWB_mm2: 16.5; Value1: Unknown; U/M: EA; Value: 1000pF; TaMax_C: 125°C; SizeZ_mm: 2.03; SizeX_mm: 4.5; SizeY_mm: 2; Value2: 2000V; SizeArea_mm2: 9; Cap_F: 1nF; AEC Category: Q200
D1 = CMP-0005599-2: Diode, TVS, Bi, 6.5 V, SMB; Manufacturer: Littelfuse; SizeZ_mm: 2.6; SizeY_mm: 3.81; Ppk: 600W; AEC Category: Q101; RJA_CperW: 100; SizeArea_mm2: 21.336; SizeX_mm: 5.6; SizeAreaWB_mm2: 44.156
J7 = CMP-0097752-1: Conn Micro USB 2.0 Type AB RCP 5 POS 0.65mm Solder RA SMD 5 Terminal 1 Port T/R; Manufacturer: Wurth Electronics; Shrouded: true; Voltage_V: 30V; Usb Standard: USB 2.0; Current_A: 1A; ContactFinish: Gold; SizeZ_mm: 3.2mm; Is Female: yes; Conn Orientation: Horizontal; AEC Qualified: No
L1 = CMP-0076826-3: Coupled inductor, 0.28 A, 0.41 ohm, SMD; Manufacturer: MuRata; Green_REACh: Passed; Green_Lifecycle: Active; AEC Category: Q200; DCR_ohm: 0.41
L2 = CMP-0063289-1: Inductor, Shielded Drum Core, Powdered Iron, 1 uH, 7 A, 0.0189 ohm, SMD; Manufacturer: Vishay-Dale; Isat: 16A @ 20% inductance drop; Irms: 7A @ 40C rise; Green_Lifecycle: Active; SizeAreaWB_mm2: 53.7782; DCR_ohm: 0.0189; Green_REACh: Passed; Value: 1uH; Imax_A: 7A; SizeZ_mm: 2; SizeX_mm: 5.49; SizeY_mm: 5.18; SizeArea_mm2: 28.4382; Ind_H: 1µH; AEC Category: Q200
R85 R87 R90 R92 R93 R132 = CMP-0026992-3: RES, 0, 5%, 0.1 W, AEC-Q200 Grade 0, 0402; Manufacturer: Panasonic; Power_W: 100mW; TempCo: 600 ppm/C; Value_Code: 0000; Value: 0; EIA_Code: E24; SizeX_mm: 1; SizeY_mm: 0.5; SizeZ_mm: 0.6; Value2: 0.1W; AEC Qualified: Y; VDC_V: 50V; AEC Category: Q200; SizeAreaWB_mm2: 3
R88 R89 R91 R128 R133 = CMP-0094798-1: Res Thick Film 0402 10K Ohm 5% 0.063W(1/16W) ±100ppm/C Pad SMD T/R; Manufacturer: YAGEO; AEC Qualified: No; Category Cd01000Bfc2916C6: Single Components; SizeZ_mm: 0.4mm; VDC_V: 50V; Category 5C6A91606D4187Ad: Resistors; TempCo: 100ppm/°C; Power_W: 63mW; Category 7542B8484461Ae85: Passive Components
R94 = CMP-0020616-3: RES, 0, 5%, 0.125 W, AEC-Q200 Grade 0, 0805; Manufacturer: Panasonic; Power_W: 125mW; TempCo: 600 ppm/C; Value_Code: 0000; Value: 0; EIA_Code: E24; SizeX_mm: 2; SizeY_mm: 1.25; SizeZ_mm: 1.45; Value2: 0.125W; SizeArea_mm2: 2.5; AEC Qualified: Y; VDC_V: 150V; AEC Category: Q200; SizeAreaWB_mm2: 6.75
R129 = CMP-0026938-5: RES, 4.7 k, 5%, 0.063 W, AEC-Q200 Grade 0, 0402; Manufacturer: Vishay-Dale; Power_W: 63mW; TempCo: 200 ppm/C; Value_Code: 4k70; Value: 4.7k; EIA_Code: E24; SizeX_mm: 1; SizeY_mm: 0.5; SizeZ_mm: 0.6; Value2: 0.063W; AEC Qualified: Y; VDC_V: 50V; AEC Category: Q200; AEC Grade: 0
SW1 SW2 = CMP-0122841-1: Dip Switch SPST 1 Position Surface Mount Slide (Standard) Actuator 25mA 24VDC; Manufacturer: C&K Components; Circuit: SPST-NO; PositionCount: 1; SizeZ_mm: 2.3mm; VDC_V: 24V; AEC Qualified: No; Coil Resistance_ohm: 100mΩ; Electromechanical Life: 1000Cycles; Standoff Height: 0.1mm
TP13 TP14 TP16 TP17 TP21 = CMP-0078143-3: TEST POINT.  No entry in BOM.
TP22 TP23 = CMP-0055139-2: Test Point, Miniature, White, TH; Manufacturer: Keystone Electronics; ContactFinish: Silver; Green_REACh: Passed; CT: TRUE; Green_Lifecycle: Active; CNHeader: FALSE
U10 = CMP-0074023-2: 2-A Step Down Converter with Selectable Switching Frequency in HotRod package, RWK0011B (VQFN-HR-11); Alternate PartNumber: TPS62097RWKT; Manufacturer: Texas Instruments; SizeZ_mm: 1.0; SizeX_mm: 2.0; SizeArea_mm2: 4.0; CompType: IC; U/M: EA; SizeAreaWB_mm2: 9.0
U11 = CMP-0122847-1: 5.5-V, 2-A, 52-mΩ load switch with adj. rise time and adj. output discharge; Manufacturer: Texas Instruments; SizeZ_mm: 1.45mm; AEC Qualified: No; Fall Time: 2us; Max Supply Voltage: 5.5V; Nominal Supply Current: 8.3-10.2uA; Number Of Drivers: 1; Rise Time: 2540us; Standoff Height: 0mm; TaMax_C: +105°C; TaMin_C: -40°C; TJmax_C: +125°C; Turn On Delay Time: 1950us
U12 = CMP-0122846-1: LDO Regulator Pos 1.1V 0.5A 4-Pin X2SON EP T/R; Manufacturer: Texas Instruments; SizeZ_mm: 0.4mm; AEC Qualified: No; Accuracy Percentage: 1.2%; Dropout Voltage: 550mV; Max Supply Voltage: 5.5V; Min Supply Voltage: 2V; Nominal Supply Current: 25uA; Number Of Outputs: 1; Output Type: Fixed; Standoff Height: 0mm; TJmax_C: +125°C
U14 = CMP-0074276-1: Single, Current-Limited, Power-Distribution Switch, DBV0005A (SOT-23-5); Alternate PartNumber: TPS2051BDBVT; Alternate Manufacturer: Texas Instruments; Green_Lifecycle: Active; SizeAreaWB_mm2: 14.82; Green_REACh: Passed; U/M: EA; SizeZ_mm: 1.45; SizeX_mm: 2.8; SizeY_mm: 2.9; SizeArea_mm2: 8.12; CompType: IC
U15 = CMP-0073612-3: 4-Channel ESD Protection Diode for USB Type-C and HDMI 2.0, DQA0010A (USON-10); Alternate Manufacturer: Texas Instruments; Green_Lifecycle: Active; SizeAreaWB_mm2: 7.0; Green_REACh: Passed; SizeZ_mm: 0.55; SizeX_mm: 1.0; SizeY_mm: 2.5; CompType: IC; AEC Category: Q200; AEC Qualified: Y

## Sheet PROC200_OSPI_FSI _DAC_Emmulator_Header.SchDoc
size 431 x 279 mm; SheetNumber: 8; SheetTotal: 18
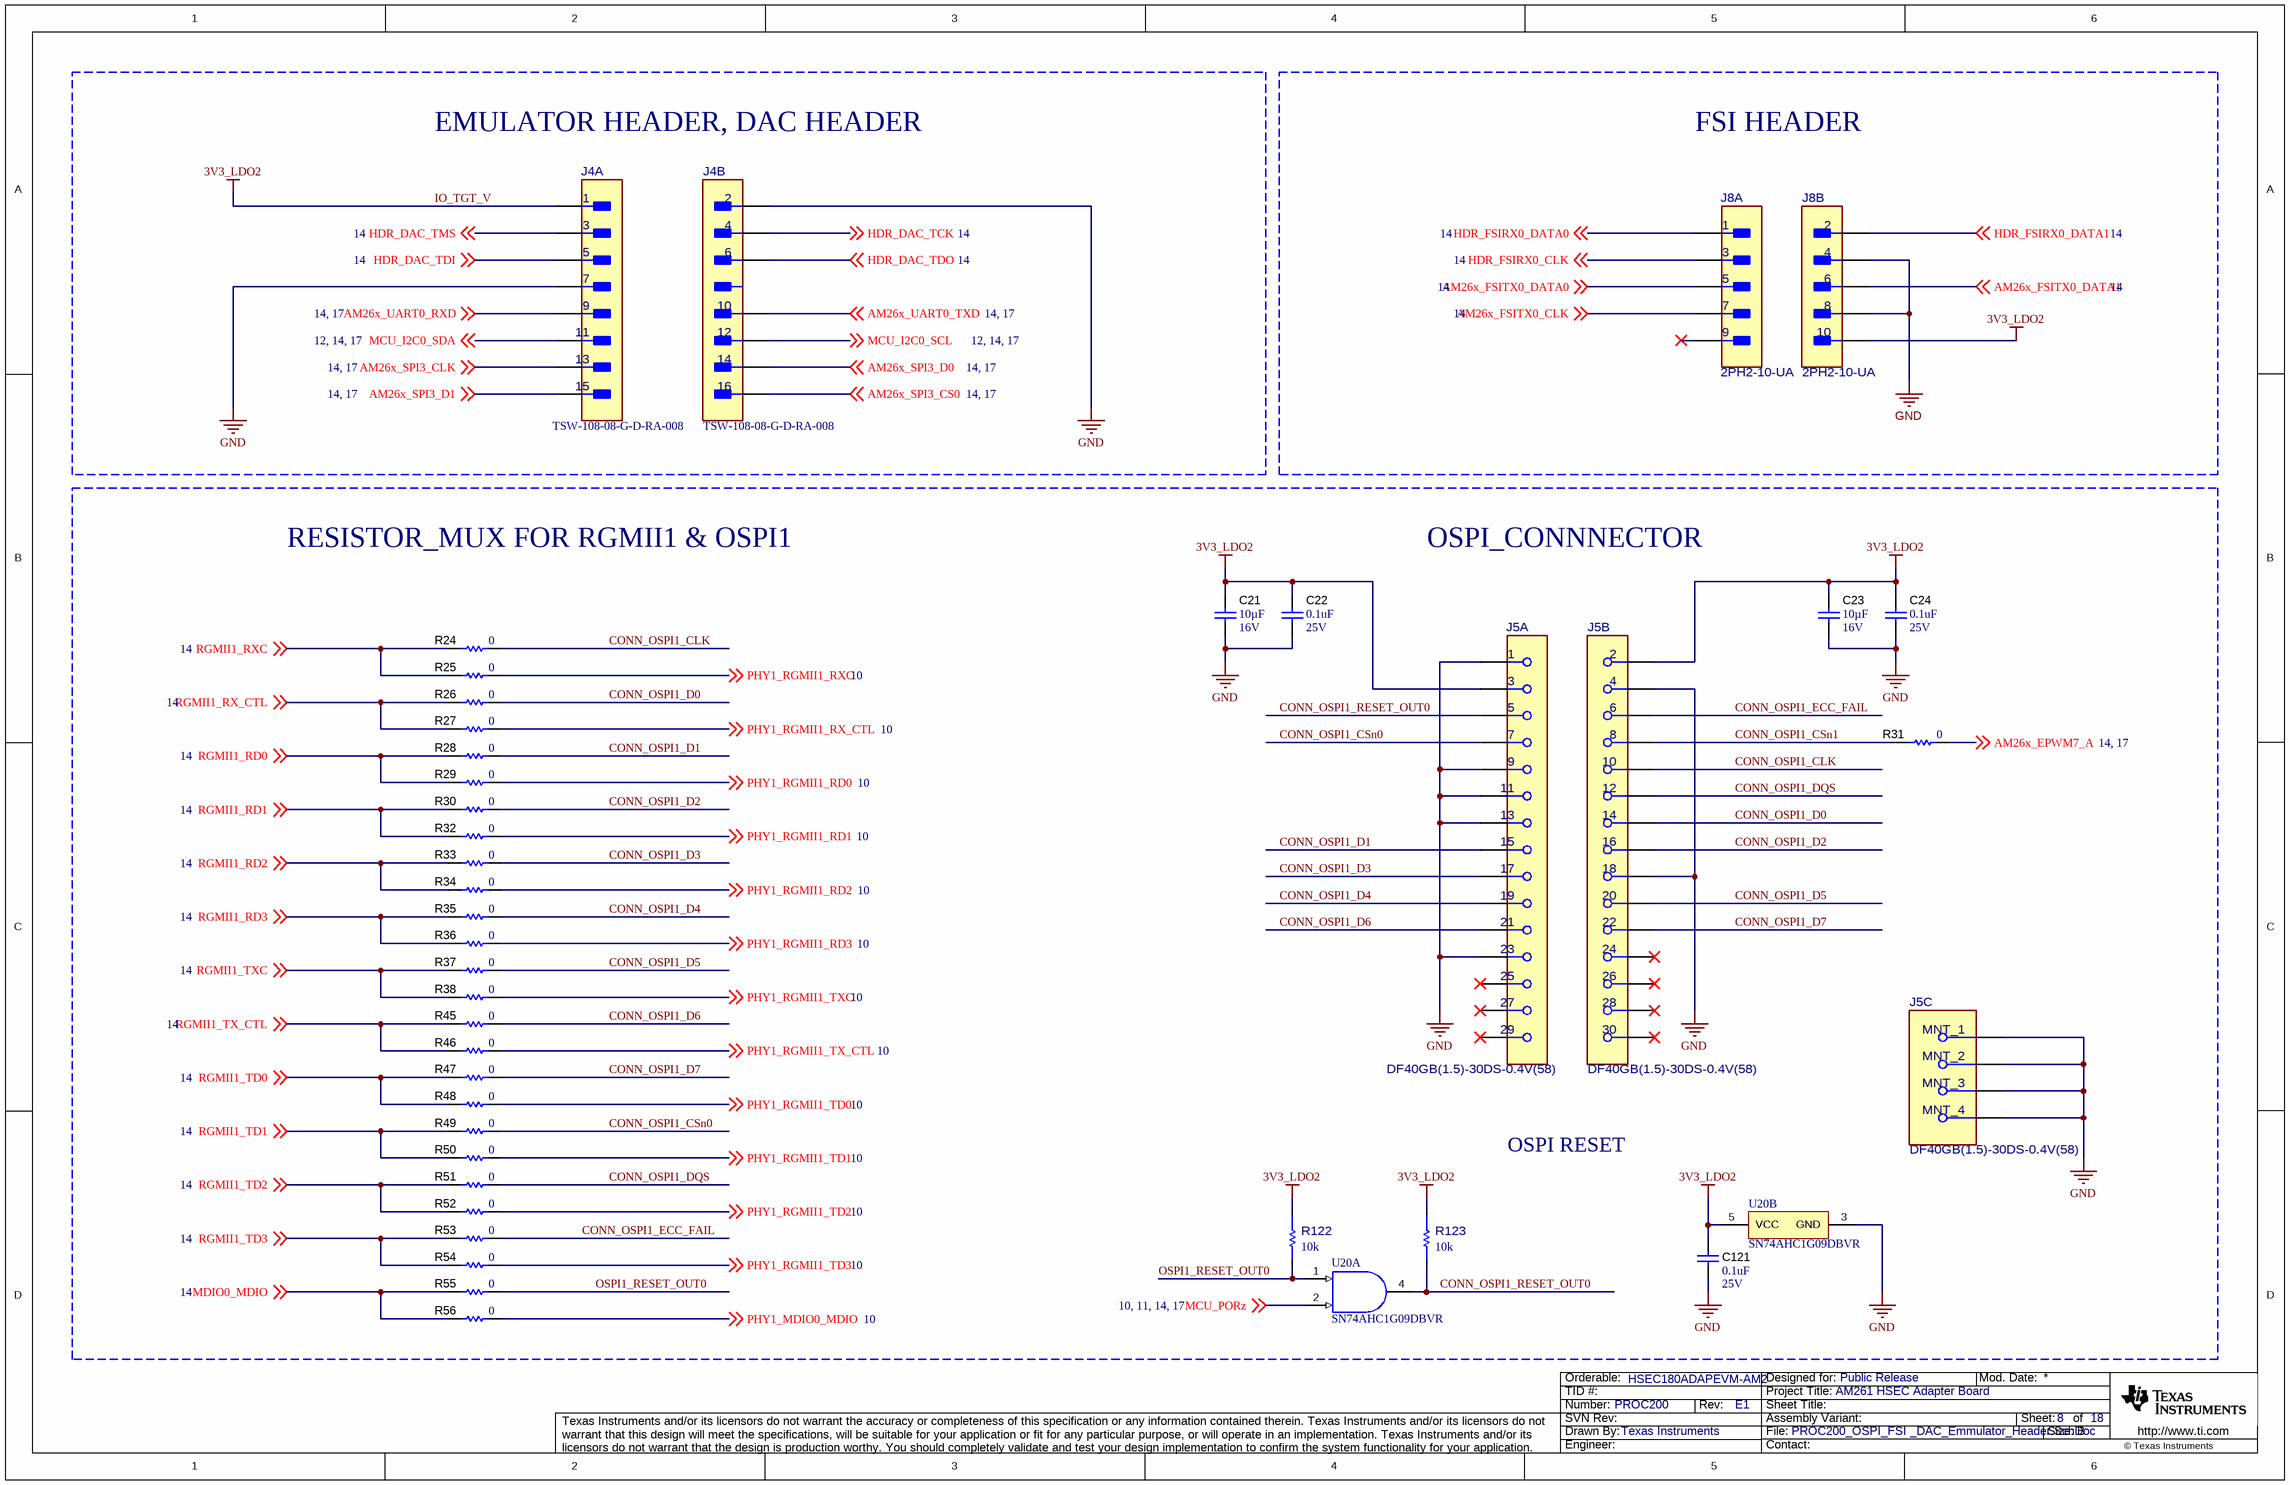
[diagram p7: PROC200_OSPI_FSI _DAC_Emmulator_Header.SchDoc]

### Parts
C21  VDC_V: 16V  ValueDisplayed: 10µF  [0603]  (hidden comment: GRM188C81C106MA73D)
C22  VDC_V: 25V  ValueDisplayed: 0.1uF  [0402]  (hidden comment: GRM155R71E104KE14D)
C23  VDC_V: 16V  ValueDisplayed: 10µF  [0603]  (hidden comment: GRM188C81C106MA73D)
C24  VDC_V: 25V  ValueDisplayed: 0.1uF  [0402]  (hidden comment: GRM155R71E104KE14D)
C121  Value2: 25V  ValueDisplayed: 0.1uF  [0402]  (hidden comment: GRM155R71E104KE14D)
J4  TSW-108-08-G-D-RA-008  [FP-TSW-108-08-G-D-RA-008_HDR15-MFG]  (parts A,B of 2)
J5  DF40GB(1.5)-30DS-0.4V(58)  [FP-DF40GB(1.5)-30DS-0.4V(58)_HDR30-MFG]  (parts A,B,C of 3)
J8  2PH2-10-UA  [FP-2PH2-10-UA_HDR10-MFG]  (parts A,B of 2)
R24  ValueDisplayed: 0  [0402]  (hidden comment: ERJ-2GE0R00X)
R25  ValueDisplayed: 0  [0402]  (hidden comment: ERJ-2GE0R00X)
R26  ValueDisplayed: 0  [0402]  (hidden comment: ERJ-2GE0R00X)
R27  ValueDisplayed: 0  [0402]  (hidden comment: ERJ-2GE0R00X)
R28  ValueDisplayed: 0  [0402]  (hidden comment: ERJ-2GE0R00X)
R29  ValueDisplayed: 0  [0402]  (hidden comment: ERJ-2GE0R00X)
R30  ValueDisplayed: 0  [0402]  (hidden comment: ERJ-2GE0R00X)
R31  ValueDisplayed: 0  [0402]  (hidden comment: ERJ-2GE0R00X)
R32  ValueDisplayed: 0  [0402]  (hidden comment: ERJ-2GE0R00X)
R33  ValueDisplayed: 0  [0402]  (hidden comment: ERJ-2GE0R00X)
R34  ValueDisplayed: 0  [0402]  (hidden comment: ERJ-2GE0R00X)
R35  ValueDisplayed: 0  [0402]  (hidden comment: ERJ-2GE0R00X)
R36  ValueDisplayed: 0  [0402]  (hidden comment: ERJ-2GE0R00X)
R37  ValueDisplayed: 0  [0402]  (hidden comment: ERJ-2GE0R00X)
R38  ValueDisplayed: 0  [0402]  (hidden comment: ERJ-2GE0R00X)
R45  ValueDisplayed: 0  [0402]  (hidden comment: ERJ-2GE0R00X)
R46  ValueDisplayed: 0  [0402]  (hidden comment: ERJ-2GE0R00X)
R47  ValueDisplayed: 0  [0402]  (hidden comment: ERJ-2GE0R00X)
R48  ValueDisplayed: 0  [0402]  (hidden comment: ERJ-2GE0R00X)
R49  ValueDisplayed: 0  [0402]  (hidden comment: ERJ-2GE0R00X)
R50  ValueDisplayed: 0  [0402]  (hidden comment: ERJ-2GE0R00X)
R51  ValueDisplayed: 0  [0402]  (hidden comment: ERJ-2GE0R00X)
R52  ValueDisplayed: 0  [0402]  (hidden comment: ERJ-2GE0R00X)
R53  ValueDisplayed: 0  [0402]  (hidden comment: ERJ-2GE0R00X)
R54  ValueDisplayed: 0  [0402]  (hidden comment: ERJ-2GE0R00X)
R55  ValueDisplayed: 0  [0402]  (hidden comment: ERJ-2GE0R00X)
R56  ValueDisplayed: 0  [0402]  (hidden comment: ERJ-2GE0R00X)
R122  value 10k  [FP-RC0402JR-0710KL_0402-MFG]  (hidden comment: RC0402JR-0710KL)
R123  value 10k  [FP-RC0402JR-0710KL_0402-MFG]  (hidden comment: RC0402JR-0710KL)
U20  SN74AHC1G09DBVR  [DBV0005A_N]  (parts A,B of 2)

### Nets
3V3_LDO2: C21.2 C22.1 C23.2 C24.1 C121.2 J4.1 J5.2 J5.3 J8.10 R122.1 R123.1 U20.5(VCC)
GND: C21.1 C22.2 C23.1 C24.2 C121.1 J4.2 J4.7 J5.1 J5.4 J5.9 J5.11 J5.13 J5.18 J5.23 J5.31(MNT_1) J5.32(MNT_2) J5.33(MNT_3) J5.34(MNT_4) J8.4 J8.8 U20.3(GND)
AM26x_EPWM7_A: R31.2 ; off-sheet AM26x_EPWM7_A
AM26x_FSITX0_CLK: J8.7 ; off-sheet AM26x_FSITX0_CLK
AM26x_FSITX0_DATA0: J8.5 ; off-sheet AM26x_FSITX0_DATA0
AM26x_FSITX0_DATA1: J8.6 ; off-sheet AM26x_FSITX0_DATA1
AM26x_SPI3_CLK: J4.13 ; off-sheet AM26x_SPI3_CLK
AM26x_SPI3_CS0: J4.16 ; off-sheet AM26x_SPI3_CS0
AM26x_SPI3_D0: J4.14 ; off-sheet AM26x_SPI3_D0
AM26x_SPI3_D1: J4.15 ; off-sheet AM26x_SPI3_D1
AM26x_UART0_RXD: J4.9 ; off-sheet AM26x_UART0_RXD
AM26x_UART0_TXD: J4.10 ; off-sheet AM26x_UART0_TXD
CONN_OSPI1_CLK: J5.10 R24.2
CONN_OSPI1_CSn0: J5.7 R49.2
CONN_OSPI1_CSn1: J5.8 R31.1
CONN_OSPI1_D0: J5.14 R26.2
CONN_OSPI1_D1: J5.15 R28.2
CONN_OSPI1_D2: J5.16 R30.2
CONN_OSPI1_D3: J5.17 R33.2
CONN_OSPI1_D4: J5.19 R35.2
CONN_OSPI1_D5: J5.20 R37.2
CONN_OSPI1_D6: J5.21 R45.2
CONN_OSPI1_D7: J5.22 R47.2
CONN_OSPI1_DQS: J5.12 R51.2
CONN_OSPI1_ECC_FAIL: J5.6 R53.2
CONN_OSPI1_RESET_OUT0: J5.5 R123.2 U20.4(Y)
HDR_DAC_TCK: J4.4 ; off-sheet HDR_DAC_TCK
HDR_DAC_TDI: J4.5 ; off-sheet HDR_DAC_TDI
HDR_DAC_TDO: J4.6 ; off-sheet HDR_DAC_TDO
HDR_DAC_TMS: J4.3 ; off-sheet HDR_DAC_TMS
HDR_FSIRX0_CLK: J8.3 ; off-sheet HDR_FSIRX0_CLK
HDR_FSIRX0_DATA0: J8.1 ; off-sheet HDR_FSIRX0_DATA0
HDR_FSIRX0_DATA1: J8.2 ; off-sheet HDR_FSIRX0_DATA1
MCU_I2C0_SCL: J4.12 ; off-sheet MCU_I2C0_SCL
MCU_I2C0_SDA: J4.11 ; off-sheet MCU_I2C0_SDA
MCU_PORz: U20.2(B) ; off-sheet MCU_PORz
MDIO0_MDIO: R55.1 R56.1 ; off-sheet MDIO0_MDIO
OSPI1_RESET_OUT0: R55.2 R122.2 U20.1(A)
PHY1_MDIO0_MDIO: R56.2 ; off-sheet PHY1_MDIO0_MDIO
PHY1_RGMII1_RD0: R29.2 ; off-sheet PHY1_RGMII1_RD0
PHY1_RGMII1_RD1: R32.2 ; off-sheet PHY1_RGMII1_RD1
PHY1_RGMII1_RD2: R34.2 ; off-sheet PHY1_RGMII1_RD2
PHY1_RGMII1_RD3: R36.2 ; off-sheet PHY1_RGMII1_RD3
PHY1_RGMII1_RX_CTL: R27.2 ; off-sheet PHY1_RGMII1_RX_CTL
PHY1_RGMII1_RXC: R25.2 ; off-sheet PHY1_RGMII1_RXC
PHY1_RGMII1_TD0: R48.2 ; off-sheet PHY1_RGMII1_TD0
PHY1_RGMII1_TD1: R50.2 ; off-sheet PHY1_RGMII1_TD1
PHY1_RGMII1_TD2: R52.2 ; off-sheet PHY1_RGMII1_TD2
PHY1_RGMII1_TD3: R54.2 ; off-sheet PHY1_RGMII1_TD3
PHY1_RGMII1_TX_CTL: R46.2 ; off-sheet PHY1_RGMII1_TX_CTL
PHY1_RGMII1_TXC: R38.2 ; off-sheet PHY1_RGMII1_TXC
RGMII1_RD0: R28.1 R29.1 ; off-sheet RGMII1_RD0
RGMII1_RD1: R30.1 R32.1 ; off-sheet RGMII1_RD1
RGMII1_RD2: R33.1 R34.1 ; off-sheet RGMII1_RD2
RGMII1_RD3: R35.1 R36.1 ; off-sheet RGMII1_RD3
RGMII1_RX_CTL: R26.1 R27.1 ; off-sheet RGMII1_RX_CTL
RGMII1_RXC: R24.1 R25.1 ; off-sheet RGMII1_RXC
RGMII1_TD0: R47.1 R48.1 ; off-sheet RGMII1_TD0
RGMII1_TD1: R49.1 R50.1 ; off-sheet RGMII1_TD1
RGMII1_TD2: R51.1 R52.1 ; off-sheet RGMII1_TD2
RGMII1_TD3: R53.1 R54.1 ; off-sheet RGMII1_TD3
RGMII1_TX_CTL: R45.1 R46.1 ; off-sheet RGMII1_TX_CTL
RGMII1_TXC: R37.1 R38.1 ; off-sheet RGMII1_TXC

Not connected (* = marked no-connect by the designer): J5 24* 25* 26* 27* 28* 29* 30*; J8 9*

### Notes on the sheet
- EMULATOR HEADER, DAC HEADER
- FSI HEADER
- IO_TGT_V
- RESISTOR_MUX FOR RGMII1 & OSPI1
- OSPI_CONNNECTOR
- OSPI RESET

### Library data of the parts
C21 C23 = CMP-0086062-1: as C72 on sheet PROC200_LDO_USB_MICRO-AB
C22 C24 = CMP-0006659-2: as C103 on sheet PROC200_LDO_USB_MICRO-AB
C121 = CMP-0006659-2: as C105 on sheet PROC200_LDO_USB_MICRO-AB
J4 = CMP-0121702-1: Connector Header Through Hole, Right Angle 16 position 0.100" (2.54mm); Manufacturer: Samtec; ContactFinish: Gold,Nickel; Row_Count: 2; AEC Qualified: No; Conn Gender: Male; SizeZ_mm: 5.21mm
J5 = CMP-0121593-1: 30 Position Connector Receptacle, Center Strip Contacts Surface Mount Gold; Manufacturer: Hirose; ContactFinish: Gold,Nickel; Current_A: 300mA; Row_Count: 2; Voltage_V: 50V; AEC Qualified: No; Conn Gender: Female; Conn Orientation: Straight; DUT-Pitch_mm: 0.4mm; Is Female: yes; SizeZ_mm: 1.6mm
J8 = CMP-0123218-1: Connector Header Through Hole 10 position 0.079" (2.00mm); Manufacturer: Adam Tech; ContactFinish: Gold,Nickel; Current_A: 1A; Row_Count: 2; AEC Qualified: No; Conn Gender: Male; Conn Orientation: Straight; DUT-Pitch_mm: 2mm; SizeZ_mm: 0.263inch
R24-R38 R45-R56 = CMP-0026992-3: as R85 on sheet PROC200_LDO_USB_MICRO-AB
R122 R123 = CMP-0094798-1: as R88 on sheet PROC200_LDO_USB_MICRO-AB
U20 = CMP-0051264-2: Single 2-Input Positive–AND Gate with Open Drain Output,  DBV0005A (SOT-23-5); Manufacturer: Texas Instruments; 3-State Output: No; Input Type: CMOS; Bits(#): 1; F @ Nom Voltage(Max)(Mhz): 75; tpd @ Nom Voltage(Max)(ns): 11,7.5; Voltage(Nom)(V): 3.3,5; Output Drive (IOL/IOH)(Max)(mA): 50/-50; Gate Type: AND; VCC(Max)(V): 5.5; ICC @ Nom Voltage(Max)(mA): 0.01; VCC(Min)(V): 2; Logic: True; Rating: Catalog; AEC Category: Q200; AEC Qualified: N; CompType: IC; SizeAreaWB_mm2: 14.82; SizeArea_mm2: 8.12; SizeX_mm: 2.8; SizeY_mm: 2.9; SizeZ_mm: 1.45

## Sheet PROC200_PHY_MUX.SchDoc
size 431 x 279 mm; Date: Not shown in title block; ApprovedBy: Not shown in title block; CheckedBy: Not shown in title block; Author: Not shown in title block; CompanyName: Not shown in title block; Engineer: Not shown in title block; Organization: Not shown in title block; Address1: Not shown in title block; Address2: Not shown in title block; Address3: Not shown in title block; Address4: Not shown in title block; DocumentNumber: 1; Revision: Use project parameter SCH_Rev; SheetNumber: 9; SheetTotal: 18; PageSetup: Record=PageOptions¦CenterHorizontal=True¦CenterVertical=True¦PrintScale=1.00¦XCorrection=1.00¦YCorrection=1.00¦PrintKind=0¦BorderSize=5000000¦LeftOffset=0¦BottomOffset=0¦Orientation=2¦PaperLength=1000¦PaperWidth=1000¦Scale=100¦PaperSource=15¦PrintQuality=600¦MediaType=1¦DitherType=10¦PaperKind=Letter¦PrintScaleMode=1
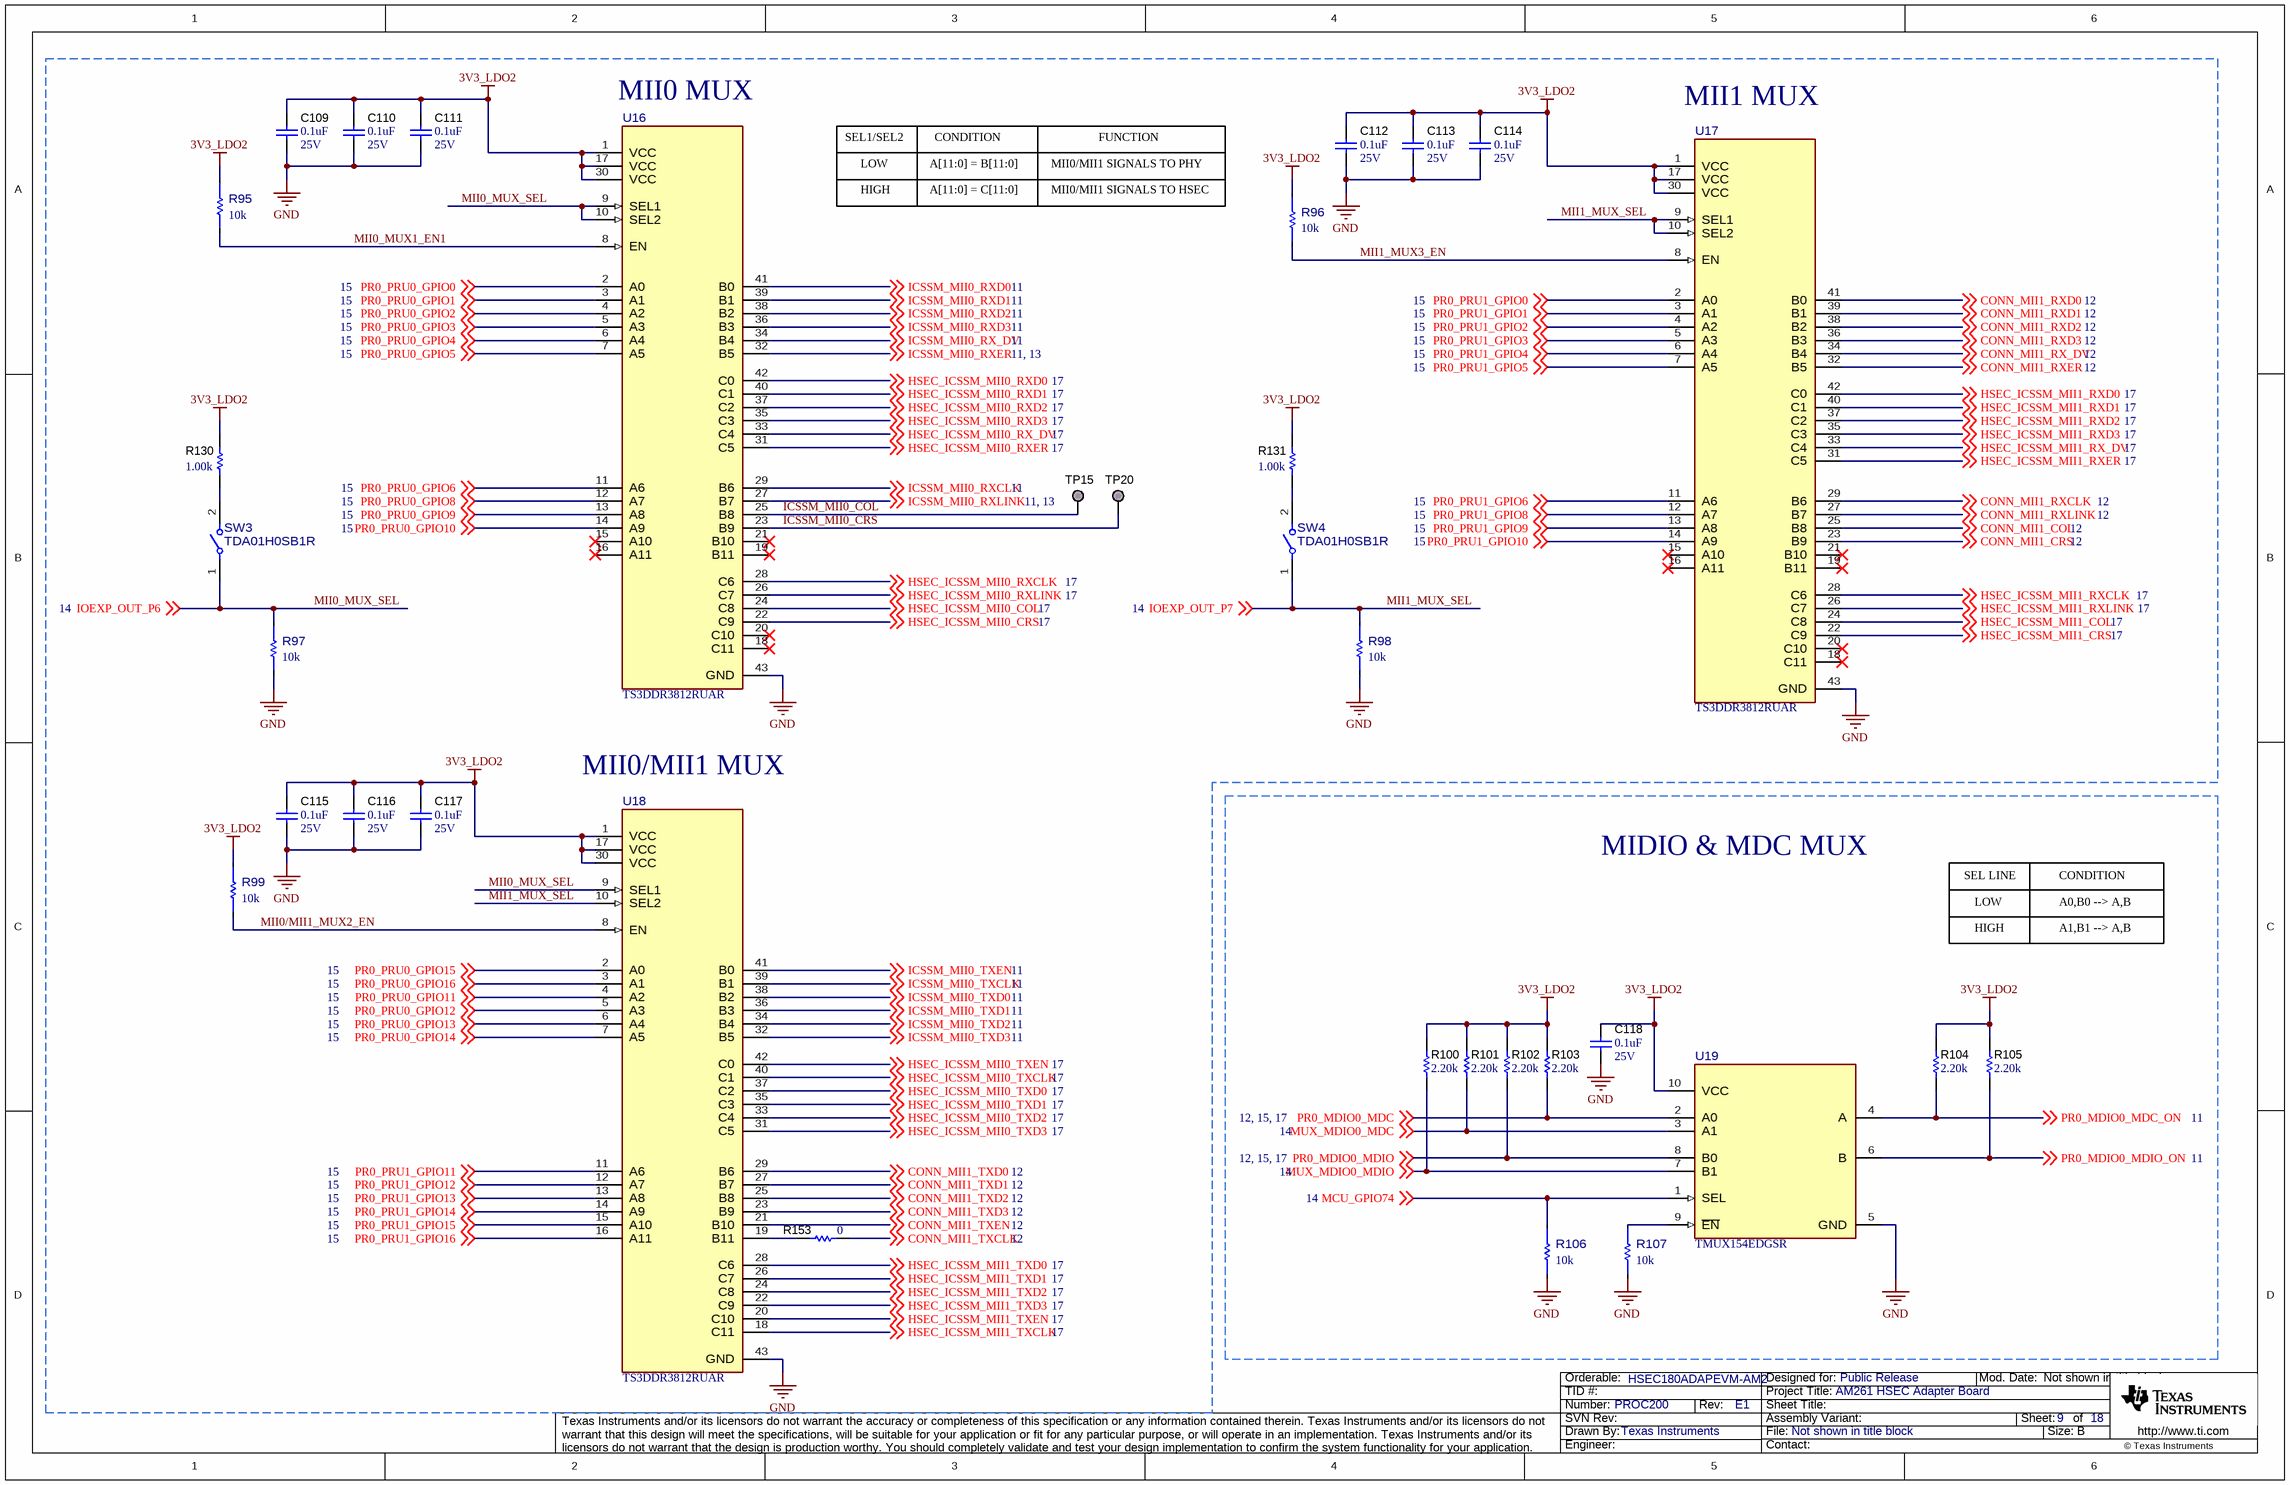
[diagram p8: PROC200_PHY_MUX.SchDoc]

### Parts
C109  VDC_V: 25V  ValueDisplayed: 0.1uF  [0402]  (hidden comment: GRM155R71E104KE14D)
C110  VDC_V: 25V  ValueDisplayed: 0.1uF  [0402]  (hidden comment: GRM155R71E104KE14D)
C111  VDC_V: 25V  ValueDisplayed: 0.1uF  [0402]  (hidden comment: GRM155R71E104KE14D)
C112  VDC_V: 25V  ValueDisplayed: 0.1uF  [0402]  (hidden comment: GRM155R71E104KE14D)
C113  VDC_V: 25V  ValueDisplayed: 0.1uF  [0402]  (hidden comment: GRM155R71E104KE14D)
C114  VDC_V: 25V  ValueDisplayed: 0.1uF  [0402]  (hidden comment: GRM155R71E104KE14D)
C115  VDC_V: 25V  ValueDisplayed: 0.1uF  [0402]  (hidden comment: GRM155R71E104KE14D)
C116  VDC_V: 25V  ValueDisplayed: 0.1uF  [0402]  (hidden comment: GRM155R71E104KE14D)
C117  VDC_V: 25V  ValueDisplayed: 0.1uF  [0402]  (hidden comment: GRM155R71E104KE14D)
C118  VDC_V: 25V  ValueDisplayed: 0.1uF  [0402]  (hidden comment: GRM155R71E104KE14D)
R95  value 10k  [FP-RC0402JR-0710KL_0402-MFG]  (hidden comment: RC0402JR-0710KL)
R96  value 10k  [FP-RC0402JR-0710KL_0402-MFG]  (hidden comment: RC0402JR-0710KL)
R97  value 10k  [FP-RC0402JR-0710KL_0402-MFG]  (hidden comment: RC0402JR-0710KL)
R98  value 10k  [FP-RC0402JR-0710KL_0402-MFG]  (hidden comment: RC0402JR-0710KL)
R99  value 10k  [FP-RC0402JR-0710KL_0402-MFG]  (hidden comment: RC0402JR-0710KL)
R100  ValueDisplayed: 2.20k  [0402]  (hidden comment: CRCW04022K20FKED)
R101  ValueDisplayed: 2.20k  [0402]  (hidden comment: CRCW04022K20FKED)
R102  ValueDisplayed: 2.20k  [0402]  (hidden comment: CRCW04022K20FKED)
R103  ValueDisplayed: 2.20k  [0402]  (hidden comment: CRCW04022K20FKED)
R104  ValueDisplayed: 2.20k  [0402]  (hidden comment: CRCW04022K20FKED)
R105  ValueDisplayed: 2.20k  [0402]  (hidden comment: CRCW04022K20FKED)
R106  value 10k  [FP-RC0402JR-0710KL_0402-MFG]  (hidden comment: RC0402JR-0710KL)
R107  value 10k  [FP-RC0402JR-0710KL_0402-MFG]  (hidden comment: RC0402JR-0710KL)
R130  ValueDisplayed: 1.00k  [0402]  (hidden comment: ERJ-2RKF1001X)
R131  ValueDisplayed: 1.00k  [0402]  (hidden comment: ERJ-2RKF1001X)
R153  ValueDisplayed: 0  [0402]  (hidden comment: ERJ-2GE0R00X)
SW3  TDA01H0SB1R  [FP-TDA01H0SB1R_SMT_SW_2MM40_6MM20-MFG]
SW4  TDA01H0SB1R  [FP-TDA01H0SB1R_SMT_SW_2MM40_6MM20-MFG]
TP15  TESTPOINT  [TP_25MIL-SMT]  (value not drawn)  (no BOM)
TP20  TESTPOINT  [TP_25MIL-SMT]  (value not drawn)  (no BOM)
U16  TS3DDR3812RUAR  [RUA0042A-MFG]
U17  TS3DDR3812RUAR  [RUA0042A-MFG]
U18  TS3DDR3812RUAR  [RUA0042A-MFG]
U19  TMUX154EDGSR  [DGS0010A-MFG]

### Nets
3V3_LDO2: C109.1 C110.1 C111.1 C112.1 C113.1 C114.1 C115.1 C116.1 C117.1 C118.1 R95.1 R96.1 R99.1 R100.2 R101.2 R102.2 R103.2 R104.2 R105.2 R130.2 R131.2 U16.1(VCC) U16.17(VCC) U16.30(VCC) U17.1(VCC) U17.17(VCC) U17.30(VCC) U18.1(VCC) U18.17(VCC) U18.30(VCC) U19.10(VCC)
GND: C109.2 C110.2 C111.2 C112.2 C113.2 C114.2 C115.2 C116.2 C117.2 C118.2 R97.2 R98.2 R106.2 R107.2 U16.43(GND) U17.43(GND) U18.43(GND) U19.5(GND)
CONN_MII1_COL: U17.25(B8) ; off-sheet CONN_MII1_COL  [project net ICSSM_MII1_COL]
CONN_MII1_CRS: U17.23(B9) ; off-sheet CONN_MII1_CRS  [project net ICSSM_MII1_CRS]
CONN_MII1_RX_DV: U17.34(B4) ; off-sheet CONN_MII1_RX_DV  [project net ICSSM_MII1_RXDV]
CONN_MII1_RXCLK: U17.29(B6) ; off-sheet CONN_MII1_RXCLK  [project net ICSSM_MII1_RXCLK]
CONN_MII1_RXD0: U17.41(B0) ; off-sheet CONN_MII1_RXD0  [project net ICSSM_MII1_RXD0]
CONN_MII1_RXD1: U17.39(B1) ; off-sheet CONN_MII1_RXD1  [project net ICSSM_MII1_RXD1]
CONN_MII1_RXD2: U17.38(B2) ; off-sheet CONN_MII1_RXD2  [project net ICSSM_MII1_RXD2]
CONN_MII1_RXD3: U17.36(B3) ; off-sheet CONN_MII1_RXD3  [project net ICSSM_MII1_RXD3]
CONN_MII1_RXER: U17.32(B5) ; off-sheet CONN_MII1_RXER  [project net ICSSM_MII1_RXER]
CONN_MII1_RXLINK: U17.27(B7) ; off-sheet CONN_MII1_RXLINK  [project net ICSSM_MII1_RXLINK]
CONN_MII1_TXCLK: R153.2 ; off-sheet CONN_MII1_TXCLK  [project net ICSSM_MII1_TXCLK]
CONN_MII1_TXD0: U18.29(B6) ; off-sheet CONN_MII1_TXD0  [project net ICSSM_MII1_TXD0]
CONN_MII1_TXD1: U18.27(B7) ; off-sheet CONN_MII1_TXD1  [project net ICSSM_MII1_TXD1]
CONN_MII1_TXD2: U18.25(B8) ; off-sheet CONN_MII1_TXD2  [project net ICSSM_MII1_TXD2]
CONN_MII1_TXD3: U18.23(B9) ; off-sheet CONN_MII1_TXD3  [project net ICSSM_MII1_TXD3]
CONN_MII1_TXEN: U18.21(B10) ; off-sheet CONN_MII1_TXEN  [project net ICSSM_MII1_TXEN]
HSEC_ICSSM_MII0_COL: U16.24(C8) ; off-sheet HSEC_ICSSM_MII0_COL
HSEC_ICSSM_MII0_CRS: U16.22(C9) ; off-sheet HSEC_ICSSM_MII0_CRS
HSEC_ICSSM_MII0_RX_DV: U16.33(C4) ; off-sheet HSEC_ICSSM_MII0_RX_DV
HSEC_ICSSM_MII0_RXCLK: U16.28(C6) ; off-sheet HSEC_ICSSM_MII0_RXCLK
HSEC_ICSSM_MII0_RXD0: U16.42(C0) ; off-sheet HSEC_ICSSM_MII0_RXD0
HSEC_ICSSM_MII0_RXD1: U16.40(C1) ; off-sheet HSEC_ICSSM_MII0_RXD1
HSEC_ICSSM_MII0_RXD2: U16.37(C2) ; off-sheet HSEC_ICSSM_MII0_RXD2
HSEC_ICSSM_MII0_RXD3: U16.35(C3) ; off-sheet HSEC_ICSSM_MII0_RXD3
HSEC_ICSSM_MII0_RXER: U16.31(C5) ; off-sheet HSEC_ICSSM_MII0_RXER
HSEC_ICSSM_MII0_RXLINK: U16.26(C7) ; off-sheet HSEC_ICSSM_MII0_RXLINK
HSEC_ICSSM_MII0_TXCLK: U18.40(C1) ; off-sheet HSEC_ICSSM_MII0_TXCLK
HSEC_ICSSM_MII0_TXD0: U18.37(C2) ; off-sheet HSEC_ICSSM_MII0_TXD0
HSEC_ICSSM_MII0_TXD1: U18.35(C3) ; off-sheet HSEC_ICSSM_MII0_TXD1
HSEC_ICSSM_MII0_TXD2: U18.33(C4) ; off-sheet HSEC_ICSSM_MII0_TXD2
HSEC_ICSSM_MII0_TXD3: U18.31(C5) ; off-sheet HSEC_ICSSM_MII0_TXD3
HSEC_ICSSM_MII0_TXEN: U18.42(C0) ; off-sheet HSEC_ICSSM_MII0_TXEN
HSEC_ICSSM_MII1_COL: U17.24(C8) ; off-sheet HSEC_ICSSM_MII1_COL
HSEC_ICSSM_MII1_CRS: U17.22(C9) ; off-sheet HSEC_ICSSM_MII1_CRS
HSEC_ICSSM_MII1_RX_DV: U17.33(C4) ; off-sheet HSEC_ICSSM_MII1_RX_DV
HSEC_ICSSM_MII1_RXCLK: U17.28(C6) ; off-sheet HSEC_ICSSM_MII1_RXCLK
HSEC_ICSSM_MII1_RXD0: U17.42(C0) ; off-sheet HSEC_ICSSM_MII1_RXD0
HSEC_ICSSM_MII1_RXD1: U17.40(C1) ; off-sheet HSEC_ICSSM_MII1_RXD1
HSEC_ICSSM_MII1_RXD2: U17.37(C2) ; off-sheet HSEC_ICSSM_MII1_RXD2
HSEC_ICSSM_MII1_RXD3: U17.35(C3) ; off-sheet HSEC_ICSSM_MII1_RXD3
HSEC_ICSSM_MII1_RXER: U17.31(C5) ; off-sheet HSEC_ICSSM_MII1_RXER
HSEC_ICSSM_MII1_RXLINK: U17.26(C7) ; off-sheet HSEC_ICSSM_MII1_RXLINK
HSEC_ICSSM_MII1_TXCLK: U18.18(C11) ; off-sheet HSEC_ICSSM_MII1_TXCLK
HSEC_ICSSM_MII1_TXD0: U18.28(C6) ; off-sheet HSEC_ICSSM_MII1_TXD0
HSEC_ICSSM_MII1_TXD1: U18.26(C7) ; off-sheet HSEC_ICSSM_MII1_TXD1
HSEC_ICSSM_MII1_TXD2: U18.24(C8) ; off-sheet HSEC_ICSSM_MII1_TXD2
HSEC_ICSSM_MII1_TXD3: U18.22(C9) ; off-sheet HSEC_ICSSM_MII1_TXD3
HSEC_ICSSM_MII1_TXEN: U18.20(C10) ; off-sheet HSEC_ICSSM_MII1_TXEN
ICSSM_MII0_COL: TP15.1 U16.25(B8)
ICSSM_MII0_CRS: TP20.1 U16.23(B9)
ICSSM_MII0_RX_DV: U16.34(B4) ; off-sheet ICSSM_MII0_RX_DV
ICSSM_MII0_RXCLK: U16.29(B6) ; off-sheet ICSSM_MII0_RXCLK
ICSSM_MII0_RXD0: U16.41(B0) ; off-sheet ICSSM_MII0_RXD0
ICSSM_MII0_RXD1: U16.39(B1) ; off-sheet ICSSM_MII0_RXD1
ICSSM_MII0_RXD2: U16.38(B2) ; off-sheet ICSSM_MII0_RXD2
ICSSM_MII0_RXD3: U16.36(B3) ; off-sheet ICSSM_MII0_RXD3
ICSSM_MII0_RXER: U16.32(B5) ; off-sheet ICSSM_MII0_RXER
ICSSM_MII0_RXLINK: U16.27(B7) ; off-sheet ICSSM_MII0_RXLINK
ICSSM_MII0_TXCLK: U18.39(B1) ; off-sheet ICSSM_MII0_TXCLK
ICSSM_MII0_TXD0: U18.38(B2) ; off-sheet ICSSM_MII0_TXD0
ICSSM_MII0_TXD1: U18.36(B3) ; off-sheet ICSSM_MII0_TXD1
ICSSM_MII0_TXD2: U18.34(B4) ; off-sheet ICSSM_MII0_TXD2
ICSSM_MII0_TXD3: U18.32(B5) ; off-sheet ICSSM_MII0_TXD3
ICSSM_MII0_TXEN: U18.41(B0) ; off-sheet ICSSM_MII0_TXEN
MCU_GPIO74: R106.1 U19.1(SEL) ; off-sheet MCU_GPIO74
MII0/MII1_MUX2_EN: R99.2 U18.8(EN)
MII0_MUX1_EN1: R95.2 U16.8(EN)
MII0_MUX_SEL: R97.1 SW3.1 U16.9(SEL1) U16.10(SEL2) U18.9(SEL1) ; off-sheet IOEXP_OUT_P6  [also labelled IOEXP_OUT_P6]
MII1_MUX3_EN: R96.2 U17.8(EN)
MII1_MUX_SEL: R98.1 SW4.1 U17.9(SEL1) U17.10(SEL2) U18.10(SEL2) ; off-sheet IOEXP_OUT_P7  [also labelled IOEXP_OUT_P7]
MUX_MDIO0_MDC: R101.1 U19.3(A1) ; off-sheet MUX_MDIO0_MDC
MUX_MDIO0_MDIO: R100.1 U19.7(B1) ; off-sheet MUX_MDIO0_MDIO
PR0_MDIO0_MDC: R103.1 U19.2(A0) ; off-sheet PR0_MDIO0_MDC
PR0_MDIO0_MDC_ON: R104.1 U19.4(A) ; off-sheet PR0_MDIO0_MDC_ON
PR0_MDIO0_MDIO: R102.1 U19.8(B0) ; off-sheet PR0_MDIO0_MDIO
PR0_MDIO0_MDIO_ON: R105.1 U19.6(B) ; off-sheet PR0_MDIO0_MDIO_ON
PR0_PRU0_GPIO0: U16.2(A0) ; off-sheet PR0_PRU0_GPIO0
PR0_PRU0_GPIO1: U16.3(A1) ; off-sheet PR0_PRU0_GPIO1
PR0_PRU0_GPIO2: U16.4(A2) ; off-sheet PR0_PRU0_GPIO2
PR0_PRU0_GPIO3: U16.5(A3) ; off-sheet PR0_PRU0_GPIO3
PR0_PRU0_GPIO4: U16.6(A4) ; off-sheet PR0_PRU0_GPIO4
PR0_PRU0_GPIO5: U16.7(A5) ; off-sheet PR0_PRU0_GPIO5
PR0_PRU0_GPIO6: U16.11(A6) ; off-sheet PR0_PRU0_GPIO6
PR0_PRU0_GPIO8: U16.12(A7) ; off-sheet PR0_PRU0_GPIO8
PR0_PRU0_GPIO9: U16.13(A8) ; off-sheet PR0_PRU0_GPIO9
PR0_PRU0_GPIO10: U16.14(A9) ; off-sheet PR0_PRU0_GPIO10
PR0_PRU0_GPIO11: U18.4(A2) ; off-sheet PR0_PRU0_GPIO11
PR0_PRU0_GPIO12: U18.5(A3) ; off-sheet PR0_PRU0_GPIO12
PR0_PRU0_GPIO13: U18.6(A4) ; off-sheet PR0_PRU0_GPIO13
PR0_PRU0_GPIO14: U18.7(A5) ; off-sheet PR0_PRU0_GPIO14
PR0_PRU0_GPIO15: U18.2(A0) ; off-sheet PR0_PRU0_GPIO15
PR0_PRU0_GPIO16: U18.3(A1) ; off-sheet PR0_PRU0_GPIO16
PR0_PRU1_GPIO0: U17.2(A0) ; off-sheet PR0_PRU1_GPIO0
PR0_PRU1_GPIO1: U17.3(A1) ; off-sheet PR0_PRU1_GPIO1
PR0_PRU1_GPIO2: U17.4(A2) ; off-sheet PR0_PRU1_GPIO2
PR0_PRU1_GPIO3: U17.5(A3) ; off-sheet PR0_PRU1_GPIO3
PR0_PRU1_GPIO4: U17.6(A4) ; off-sheet PR0_PRU1_GPIO4
PR0_PRU1_GPIO5: U17.7(A5) ; off-sheet PR0_PRU1_GPIO5
PR0_PRU1_GPIO6: U17.11(A6) ; off-sheet PR0_PRU1_GPIO6
PR0_PRU1_GPIO8: U17.12(A7) ; off-sheet PR0_PRU1_GPIO8
PR0_PRU1_GPIO9: U17.13(A8) ; off-sheet PR0_PRU1_GPIO9
PR0_PRU1_GPIO10: U17.14(A9) ; off-sheet PR0_PRU1_GPIO10
PR0_PRU1_GPIO11: U18.11(A6) ; off-sheet PR0_PRU1_GPIO11
PR0_PRU1_GPIO12: U18.12(A7) ; off-sheet PR0_PRU1_GPIO12
PR0_PRU1_GPIO13: U18.13(A8) ; off-sheet PR0_PRU1_GPIO13
PR0_PRU1_GPIO14: U18.14(A9) ; off-sheet PR0_PRU1_GPIO14
PR0_PRU1_GPIO15: U18.15(A10) ; off-sheet PR0_PRU1_GPIO15
PR0_PRU1_GPIO16: U18.16(A11) ; off-sheet PR0_PRU1_GPIO16
NetR107_1: R107.1 U19.9(~{EN})
NetR130_1: R130.1 SW3.2
NetR131_1: R131.1 SW4.2
NetR153_1: R153.1 U18.19(B11)

Not connected (* = marked no-connect by the designer): U16 15(A10)* 16(A11)* 18(C11)* 19(B11)* 20(C10)* 21(B10)*; U17 15(A10)* 16(A11)* 18(C11)* 19(B11)* 20(C10)* 21(B10)*

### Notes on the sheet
- (near U16) MII0 MUX
- SEL1/SEL2
- LOW
- A[11:0] = B[11:0]
- CONDITION
- MII0/MII1 SIGNALS TO PHY
- FUNCTION
- (near U17) MII1 MUX
- HIGH
- A[11:0] = C[11:0]
- MII0/MII1 SIGNALS TO HSEC
- MII0/MII1 MUX
- MIDIO & MDC MUX
- SEL LINE
- A0,B0 --> A,B
- A1,B1 --> A,B

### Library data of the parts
C109-C118 = CMP-0006659-2: as C103 on sheet PROC200_LDO_USB_MICRO-AB
R95-R99 R106 R107 = CMP-0094798-1: as R88 on sheet PROC200_LDO_USB_MICRO-AB
R100-R105 = CMP-0026231-2: RES, 2.20 k, 1%, 0.063 W, AEC-Q200 Grade 0, 0402; Manufacturer: Vishay-Dale; Power_W: 63mW; TempCo: 100 ppm/C; Value_Code: 2k20; Value: 2.20k; Res_ohm: 2.2k; SizeX_mm: 1; SizeY_mm: 0.5; SizeZ_mm: 0.6; Value2: 0.063W; AEC Qualified: Y; AEC Category: Q200; AEC Grade: 0
R130 R131 = CMP-0026657-1: RES, 1.00 k, 1%, 0.1 W, 0402; Manufacturer: Panasonic; Value_Code: 1k00; SizeArea_mm2: 0.5; AEC Category: Q200; Res_ohm: 1k; Value: 1.00k; SizeZ_mm: 0.6; EIA_Code: E96; TempCo: 100 ppm/C; Power_W: 100mW; VDC_V: 50V; Value2: 0.1W; U/M: EA; SizeX_mm: 1
R153 = CMP-0026992-3: as R85 on sheet PROC200_LDO_USB_MICRO-AB
SW3 SW4 = CMP-0122841-1: as SW1 on sheet PROC200_LDO_USB_MICRO-AB
TP15 TP20 = CMP-0078143-3: TEST POINT.  No entry in BOM.
U16-U18 = CMP-0093539-2: IC MUX/DEMUX DDR3 1:2 42WQFN; Manufacturer: Texas Instruments; TaMax_C: +85°C; AEC Qualified: No; Nominal Supply Current: 300uA; On State Resistance: 8Ω; Standoff Height: 0mm; Min Supply Voltage: 3V; Max Supply Voltage: 3.6V; AEC Category: Q200; SizeZ_mm: 0.8mm; TaMin_C: -40°C; PositionCount: 12; -3Db Bandwith: 1.675GHz
U19 = CMP-0122044-1: ESD-Protected, Low Capacitance, 2-Channel, 2:1 Switch, With Powered-off Protection; Manufacturer: Texas Instruments; SizeZ_mm: 1.1mm; AEC Qualified: No; -3Db Bandwith: 900MHz; Max Supply Voltage: 4.3V; Min Supply Voltage: 3V; Nominal Supply Current: 1uA; On State Resistance: 6Ω; PositionCount: 2; Standoff Height: 0.05mm; TaMax_C: +85°C; TaMin_C: -40°C

## Sheet PROC200_RGMII1_PHY1.SchDoc
size 431 x 279 mm; SheetNumber: 10; SheetTotal: 18
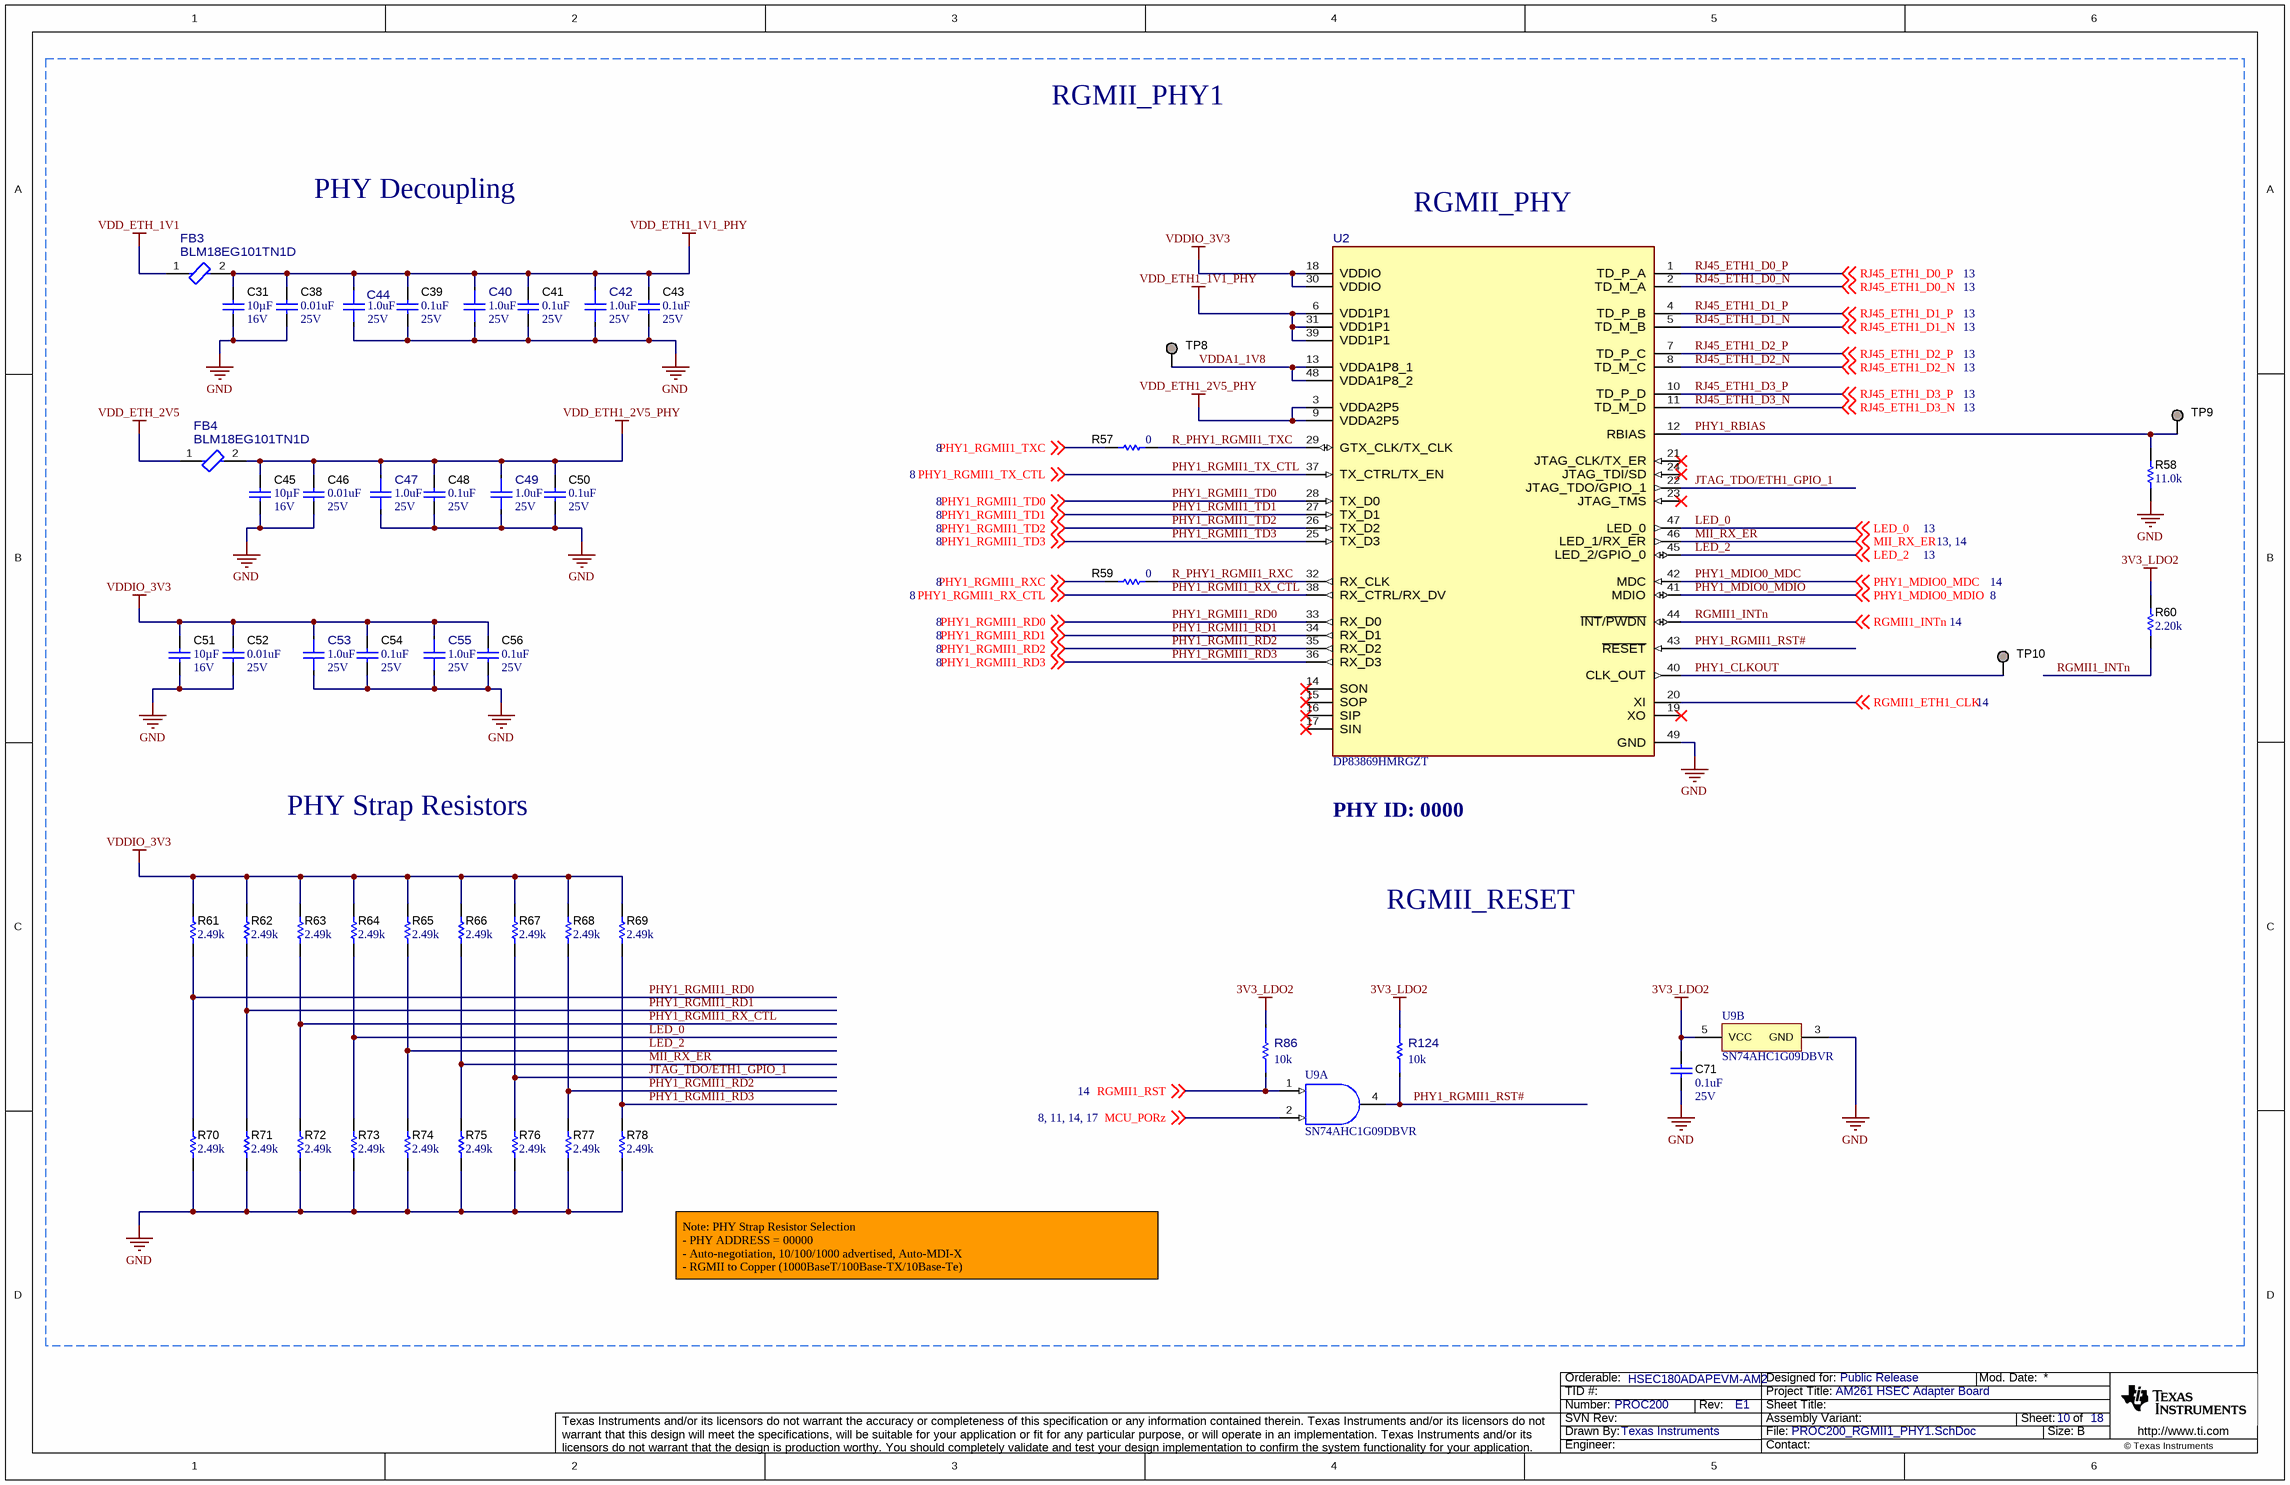
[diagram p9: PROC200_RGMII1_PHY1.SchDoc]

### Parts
C31  VDC_V: 16V  ValueDisplayed: 10µF  [0603]  (hidden comment: GRM188C81C106MA73D)
C38  Value2: 25V  ValueDisplayed: 0.01uF  [0402]  (hidden comment: GCM155R71E103KA37D)
C39  VDC_V: 25V  ValueDisplayed: 0.1uF  [0402]  (hidden comment: GRM155R71E104KE14D)
C40  ValueDisplayed: 1.0uF  VDC_V: 25V  [FP-GRM155C81E105KE11D_0402-MFG]  (hidden comment: GRM155C81E105KE11D)
C41  VDC_V: 25V  ValueDisplayed: 0.1uF  [0402]  (hidden comment: GRM155R71E104KE14D)
C42  ValueDisplayed: 1.0uF  VDC_V: 25V  [FP-GRM155C81E105KE11D_0402-MFG]  (hidden comment: GRM155C81E105KE11D)
C43  VDC_V: 25V  ValueDisplayed: 0.1uF  [0402]  (hidden comment: GRM155R71E104KE14D)
C44  ValueDisplayed: 1.0uF  VDC_V: 25V  [FP-GRM155C81E105KE11D_0402-MFG]  (hidden comment: GRM155C81E105KE11D)
C45  VDC_V: 16V  ValueDisplayed: 10µF  [0603]  (hidden comment: GRM188C81C106MA73D)
C46  Value2: 25V  ValueDisplayed: 0.01uF  [0402]  (hidden comment: GCM155R71E103KA37D)
C47  ValueDisplayed: 1.0uF  VDC_V: 25V  [FP-GRM155C81E105KE11D_0402-MFG]  (hidden comment: GRM155C81E105KE11D)
C48  VDC_V: 25V  ValueDisplayed: 0.1uF  [0402]  (hidden comment: GRM155R71E104KE14D)
C49  ValueDisplayed: 1.0uF  VDC_V: 25V  [FP-GRM155C81E105KE11D_0402-MFG]  (hidden comment: GRM155C81E105KE11D)
C50  VDC_V: 25V  ValueDisplayed: 0.1uF  [0402]  (hidden comment: GRM155R71E104KE14D)
C51  VDC_V: 16V  ValueDisplayed: 10µF  [0603]  (hidden comment: GRM188C81C106MA73D)
C52  Value2: 25V  ValueDisplayed: 0.01uF  [0402]  (hidden comment: GCM155R71E103KA37D)
C53  ValueDisplayed: 1.0uF  VDC_V: 25V  [FP-GRM155C81E105KE11D_0402-MFG]  (hidden comment: GRM155C81E105KE11D)
C54  VDC_V: 25V  ValueDisplayed: 0.1uF  [0402]  (hidden comment: GRM155R71E104KE14D)
C55  ValueDisplayed: 1.0uF  VDC_V: 25V  [FP-GRM155C81E105KE11D_0402-MFG]  (hidden comment: GRM155C81E105KE11D)
C56  VDC_V: 25V  ValueDisplayed: 0.1uF  [0402]  (hidden comment: GRM155R71E104KE14D)
C71  Value2: 25V  ValueDisplayed: 0.1uF  [0402]  (hidden comment: GRM155R71E104KE14D)
FB3  BLM18EG101TN1D  [FP-BLM18EG101TN1D_0603-MFG]
FB4  BLM18EG101TN1D  [FP-BLM18EG101TN1D_0603-MFG]
R57  ValueDisplayed: 0  [0402]  (hidden comment: ERJ-2GE0R00X)
R58  ValueDisplayed: 11.0k  [0402]  (hidden comment: CRCW040211K0FKED)
R59  ValueDisplayed: 0  [0402]  (hidden comment: ERJ-2GE0R00X)
R60  ValueDisplayed: 2.20k  [0402]  (hidden comment: CRCW04022K20FKED)
R61  ValueDisplayed: 2.49k  [0402]  (hidden comment: CRCW04022K49FKED)
R62  ValueDisplayed: 2.49k  [0402]  (hidden comment: CRCW04022K49FKED)
R63  ValueDisplayed: 2.49k  [0402]  (hidden comment: CRCW04022K49FKED)
R64  ValueDisplayed: 2.49k  [0402]  (hidden comment: CRCW04022K49FKED)
R65  ValueDisplayed: 2.49k  [0402]  (hidden comment: CRCW04022K49FKED)
R66  ValueDisplayed: 2.49k  [0402]  (hidden comment: CRCW04022K49FKED)
R67  ValueDisplayed: 2.49k  [0402]  (hidden comment: CRCW04022K49FKED)
R68  ValueDisplayed: 2.49k  [0402]  (hidden comment: CRCW04022K49FKED)
R69  ValueDisplayed: 2.49k  [0402]  (hidden comment: CRCW04022K49FKED)
R70  ValueDisplayed: 2.49k  [0402]  (hidden comment: CRCW04022K49FKED)
R71  ValueDisplayed: 2.49k  [0402]  (hidden comment: CRCW04022K49FKED)
R72  ValueDisplayed: 2.49k  [0402]  (hidden comment: CRCW04022K49FKED)
R73  ValueDisplayed: 2.49k  [0402]  (hidden comment: CRCW04022K49FKED)
R74  ValueDisplayed: 2.49k  [0402]  (hidden comment: CRCW04022K49FKED)
R75  ValueDisplayed: 2.49k  [0402]  (hidden comment: CRCW04022K49FKED)
R76  ValueDisplayed: 2.49k  [0402]  (hidden comment: CRCW04022K49FKED)
R77  ValueDisplayed: 2.49k  [0402]  (hidden comment: CRCW04022K49FKED)
R78  ValueDisplayed: 2.49k  [0402]  (hidden comment: CRCW04022K49FKED)
R86  value 10k  [FP-RC0402JR-0710KL_0402-MFG]  (hidden comment: RC0402JR-0710KL)
R124  value 10k  [FP-RC0402JR-0710KL_0402-MFG]  (hidden comment: RC0402JR-0710KL)
TP8  TESTPOINT  [TP_25MIL-SMT]  (value not drawn)  (no BOM)
TP9  TESTPOINT  [TP_25MIL-SMT]  (value not drawn)  (no BOM)
TP10  TESTPOINT  [TP_25MIL-SMT]  (value not drawn)  (no BOM)
U2  DP83869HMRGZT  [RGZ0048B-MFG]
U9  SN74AHC1G09DBVR  [DBV0005A_N]  (parts A,B of 2)

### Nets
3V3_LDO2: C71.2 R60.2 R86.1 R124.1 U9.5(VCC)
GND: C31.1 C38.2 C39.2 C40.2 C41.2 C42.2 C43.2 C44.2 C45.1 C46.2 C47.2 C48.2 C49.2 C50.2 C51.1 C52.2 C53.2 C54.2 C55.2 C56.2 C71.1 R58.2 R70.1 R71.1 R72.1 R73.1 R74.1 R75.1 R76.1 R77.1 R78.1 U2.49(GND) U9.3(GND)
VDD_ETH1_1V1_PHY: C31.2 C38.1 C39.1 C40.1 C41.1 C42.1 C43.1 C44.1 FB3.2 U2.6(VDD1P1) U2.31(VDD1P1) U2.39(VDD1P1)
VDD_ETH1_2V5_PHY: C45.2 C46.1 C47.1 C48.1 C49.1 C50.1 FB4.2 U2.3(VDDA2P5) U2.9(VDDA2P5)
VDD_ETH_1V1: FB3.1
VDD_ETH_2V5: FB4.1
VDDIO_3V3: C51.2 C52.1 C53.1 C54.1 C55.1 C56.1 R61.2 R62.2 R63.2 R64.2 R65.2 R66.2 R67.2 R68.2 R69.2 U2.18(VDDIO) U2.30(VDDIO)
JTAG_TDO/ETH1_GPIO_1: R67.1 R76.2 U2.22(JTAG_TDO/GPIO_1)
LED_0: R64.1 R73.2 U2.47(LED_0) ; off-sheet LED_0
LED_2: R65.1 R74.2 U2.45(LED_2/GPIO_0) ; off-sheet LED_2
MCU_PORz: U9.2(B) ; off-sheet MCU_PORz
MII_RX_ER: R66.1 R75.2 U2.46(LED_1/RX_ER) ; off-sheet MII_RX_ER
PHY1_CLKOUT: TP10.1 U2.40(CLK_OUT)
PHY1_MDIO0_MDC: U2.42(MDC) ; off-sheet PHY1_MDIO0_MDC
PHY1_MDIO0_MDIO: U2.41(MDIO) ; off-sheet PHY1_MDIO0_MDIO
PHY1_RBIAS: R58.1 TP9.1 U2.12(RBIAS)
PHY1_RGMII1_RD0: R61.1 R70.2 U2.33(RX_D0) ; off-sheet PHY1_RGMII1_RD0
PHY1_RGMII1_RD1: R62.1 R71.2 U2.34(RX_D1) ; off-sheet PHY1_RGMII1_RD1
PHY1_RGMII1_RD2: R68.1 R77.2 U2.35(RX_D2) ; off-sheet PHY1_RGMII1_RD2
PHY1_RGMII1_RD3: R69.1 R78.2 U2.36(RX_D3) ; off-sheet PHY1_RGMII1_RD3
PHY1_RGMII1_RST#: R124.2 U2.43(~{RESET}) U9.4(Y)
PHY1_RGMII1_RX_CTL: R63.1 R72.2 U2.38(RX_CTRL/RX_DV) ; off-sheet PHY1_RGMII1_RX_CTL
PHY1_RGMII1_RXC: R59.1 ; off-sheet PHY1_RGMII1_RXC
PHY1_RGMII1_TD0: U2.28(TX_D0) ; off-sheet PHY1_RGMII1_TD0
PHY1_RGMII1_TD1: U2.27(TX_D1) ; off-sheet PHY1_RGMII1_TD1
PHY1_RGMII1_TD2: U2.26(TX_D2) ; off-sheet PHY1_RGMII1_TD2
PHY1_RGMII1_TD3: U2.25(TX_D3) ; off-sheet PHY1_RGMII1_TD3
PHY1_RGMII1_TX_CTL: U2.37(TX_CTRL/TX_EN) ; off-sheet PHY1_RGMII1_TX_CTL
PHY1_RGMII1_TXC: R57.1 ; off-sheet PHY1_RGMII1_TXC
R_PHY1_RGMII1_RXC: R59.2 U2.32(RX_CLK)
R_PHY1_RGMII1_TXC: R57.2 U2.29(GTX_CLK/TX_CLK)
RGMII1_ETH1_CLK: U2.20(XI) ; off-sheet RGMII1_ETH1_CLK
RGMII1_INTn: R60.1 U2.44(~{INT}/~{PWDN}) ; off-sheet RGMII1_INTn
RGMII1_RST: R86.2 U9.1(A) ; off-sheet RGMII1_RST
RJ45_ETH1_D0_N: U2.2(TD_M_A) ; off-sheet RJ45_ETH1_D0_N
RJ45_ETH1_D0_P: U2.1(TD_P_A) ; off-sheet RJ45_ETH1_D0_P
RJ45_ETH1_D1_N: U2.5(TD_M_B) ; off-sheet RJ45_ETH1_D1_N
RJ45_ETH1_D1_P: U2.4(TD_P_B) ; off-sheet RJ45_ETH1_D1_P
RJ45_ETH1_D2_N: U2.8(TD_M_C) ; off-sheet RJ45_ETH1_D2_N
RJ45_ETH1_D2_P: U2.7(TD_P_C) ; off-sheet RJ45_ETH1_D2_P
RJ45_ETH1_D3_N: U2.11(TD_M_D) ; off-sheet RJ45_ETH1_D3_N
RJ45_ETH1_D3_P: U2.10(TD_P_D) ; off-sheet RJ45_ETH1_D3_P
VDDA1_1V8: TP8.1 U2.13(VDDA1P8_1) U2.48(VDDA1P8_2)

Not connected (* = marked no-connect by the designer): U2 14(SON)* 15(SOP)* 16(SIP)* 17(SIN)* 19(XO)* 21(JTAG_CLK/TX_ER)* 23(JTAG_TMS)* 24(JTAG_TDI/SD)*

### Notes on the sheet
- RGMII_PHY1
- PHY Decoupling
- RGMII_PHY
- PHY Strap Resistors
- PHY ID: 0000
- RGMII_RESET
- Note: PHY Strap Resistor Selection
  - PHY ADDRESS = 00000
  - Auto-negotiation, 10/100/1000 advertised, Auto-MDI-X
  - RGMII to Copper (1000BaseT/100Base-TX/10Base-Te)

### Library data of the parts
C31 C45 C51 = CMP-0086062-1: as C72 on sheet PROC200_LDO_USB_MICRO-AB
C38 C46 C52 = CMP-0006352-2: as C75 on sheet PROC200_LDO_USB_MICRO-AB
C39 C41 C43 C48 C50 C54 C56 = CMP-0006659-2: as C103 on sheet PROC200_LDO_USB_MICRO-AB
C40 C42 C44 C47 C49 C53 C55 = CMP-0121658-2: as C76 on sheet PROC200_LDO_USB_MICRO-AB
C71 = CMP-0006659-2: as C105 on sheet PROC200_LDO_USB_MICRO-AB
FB3 FB4 = CMP-0122093-1: Chip Ferrite Bead, 0603, 100Ω @ 100MHz, 25%, 0.045Ω, 2A; Manufacturer: Murata; DCR_ohm: 45m; SizeZ_mm: 0.65mm; AEC Qualified: No
R57 R59 = CMP-0026992-3: as R85 on sheet PROC200_LDO_USB_MICRO-AB
R58 = CMP-0025975-3: RES, 11.0 k, 1%, 0.063 W, AEC-Q200 Grade 0, 0402; Manufacturer: Vishay-Dale; Power_W: 63mW; TempCo: 100 ppm/C; Value_Code: 11k0; Value: 11.0k; EIA_Code: E96; Res_ohm: 11k; SizeX_mm: 1; SizeY_mm: 0.5; SizeZ_mm: 0.6; Value2: 0.063W; AEC Qualified: Y; VDC_V: 50V; AEC Category: Q200; AEC Grade: 0
R60 = CMP-0026231-2: as R100 on sheet PROC200_PHY_MUX
R61-R78 = CMP-0026237-2: RES, 2.49 k, 1%, 0.063 W, AEC-Q200 Grade 0, 0402; Manufacturer: Vishay-Dale; Power_W: 63mW; TempCo: 100 ppm/C; Value_Code: 2k49; Value: 2.49k; EIA_Code: E96; SizeX_mm: 1; SizeY_mm: 0.5; SizeZ_mm: 0.6; Value2: 0.063W; AEC Qualified: Y; VDC_V: 50V; AEC Category: Q200; AEC Grade: 0
R86 R124 = CMP-0094798-1: as R88 on sheet PROC200_LDO_USB_MICRO-AB
TP8-TP10 = CMP-0078143-3: TEST POINT.  No entry in BOM.
U2 = CMP-0091377-1: 1/1 Transceiver Ethernet 48-VQFN (7x7); Manufacturer: Texas Instruments; TaMin_C: -40°C; SizeZ_mm: 1mm; TaMax_C: +125°C; Max Supply Voltage: 3.45V; Number Of Channels: 1; AEC Qualified: No; Data Rate: 1000Mbits/s; Min Supply Voltage: 990mV; Simplex Duplex: Full-Duplex; Standoff Height: 0mm
U9 = CMP-0051264-2: as U20 on sheet PROC200_OSPI_FSI _DAC_Emmulator_Header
